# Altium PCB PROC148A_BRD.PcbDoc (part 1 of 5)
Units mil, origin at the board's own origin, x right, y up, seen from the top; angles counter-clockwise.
Board outline 7150 x 3764 mil, 4 copper layers (Top Layer, GND01, PWR/GND02, Bottom Layer), stack 60.96 mil thick; 312 components, 352 nets, 2206 pads, 423 vias.
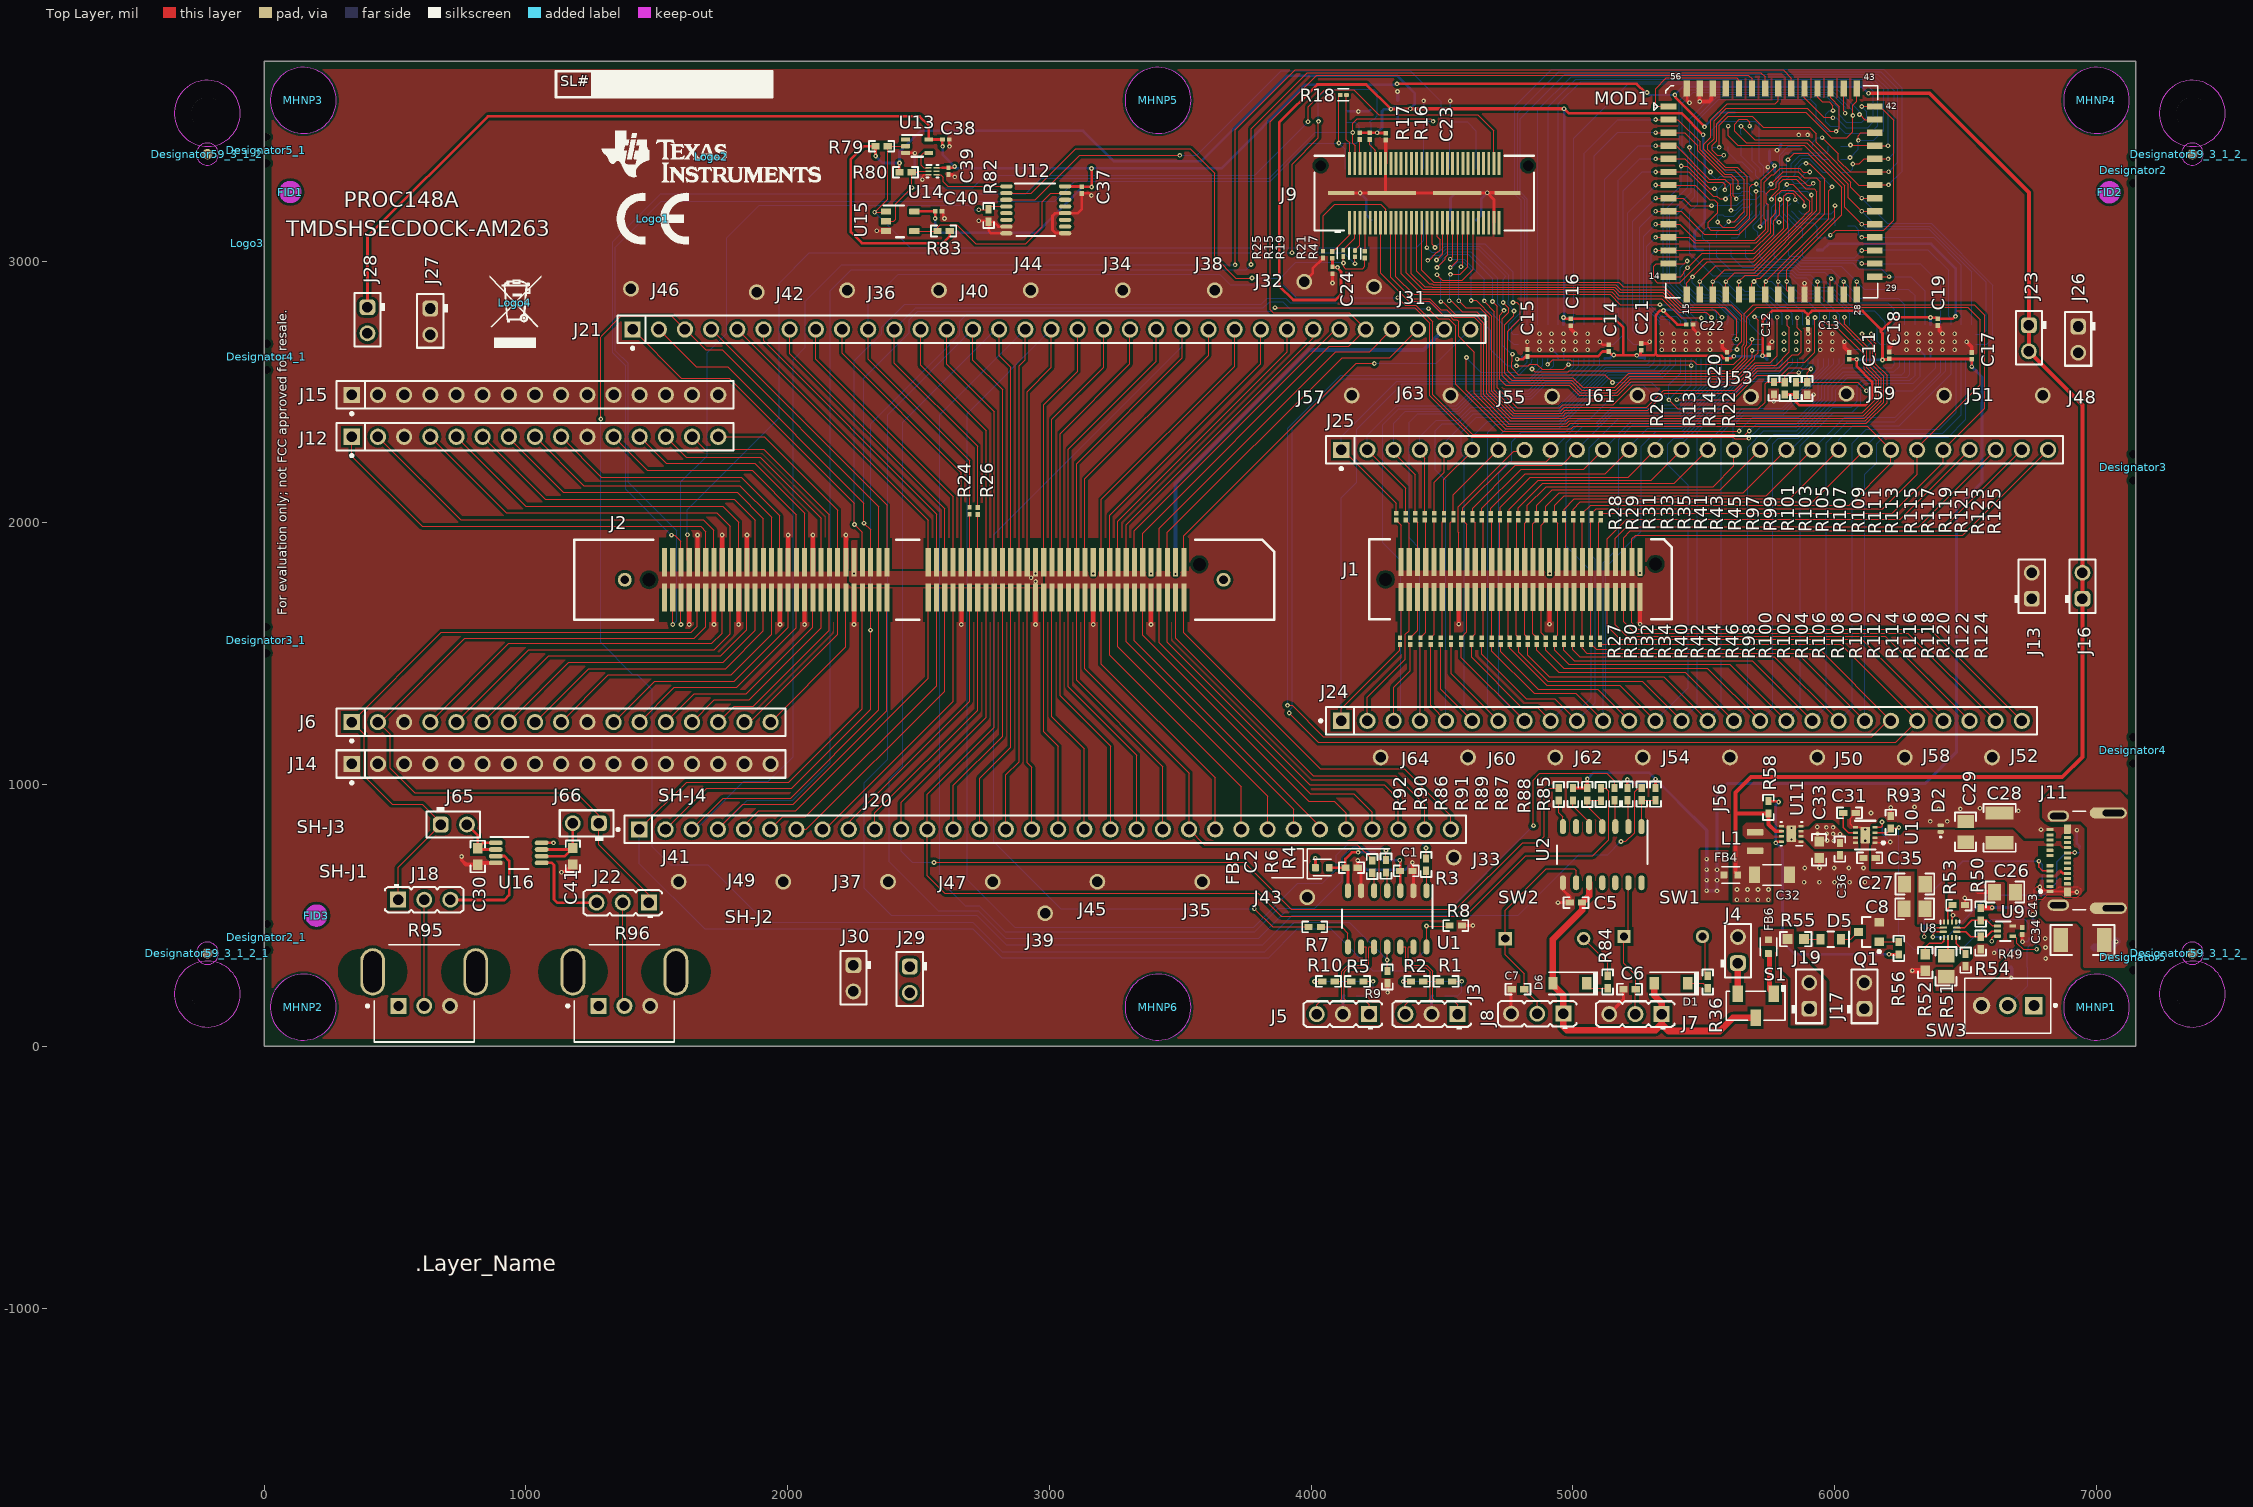
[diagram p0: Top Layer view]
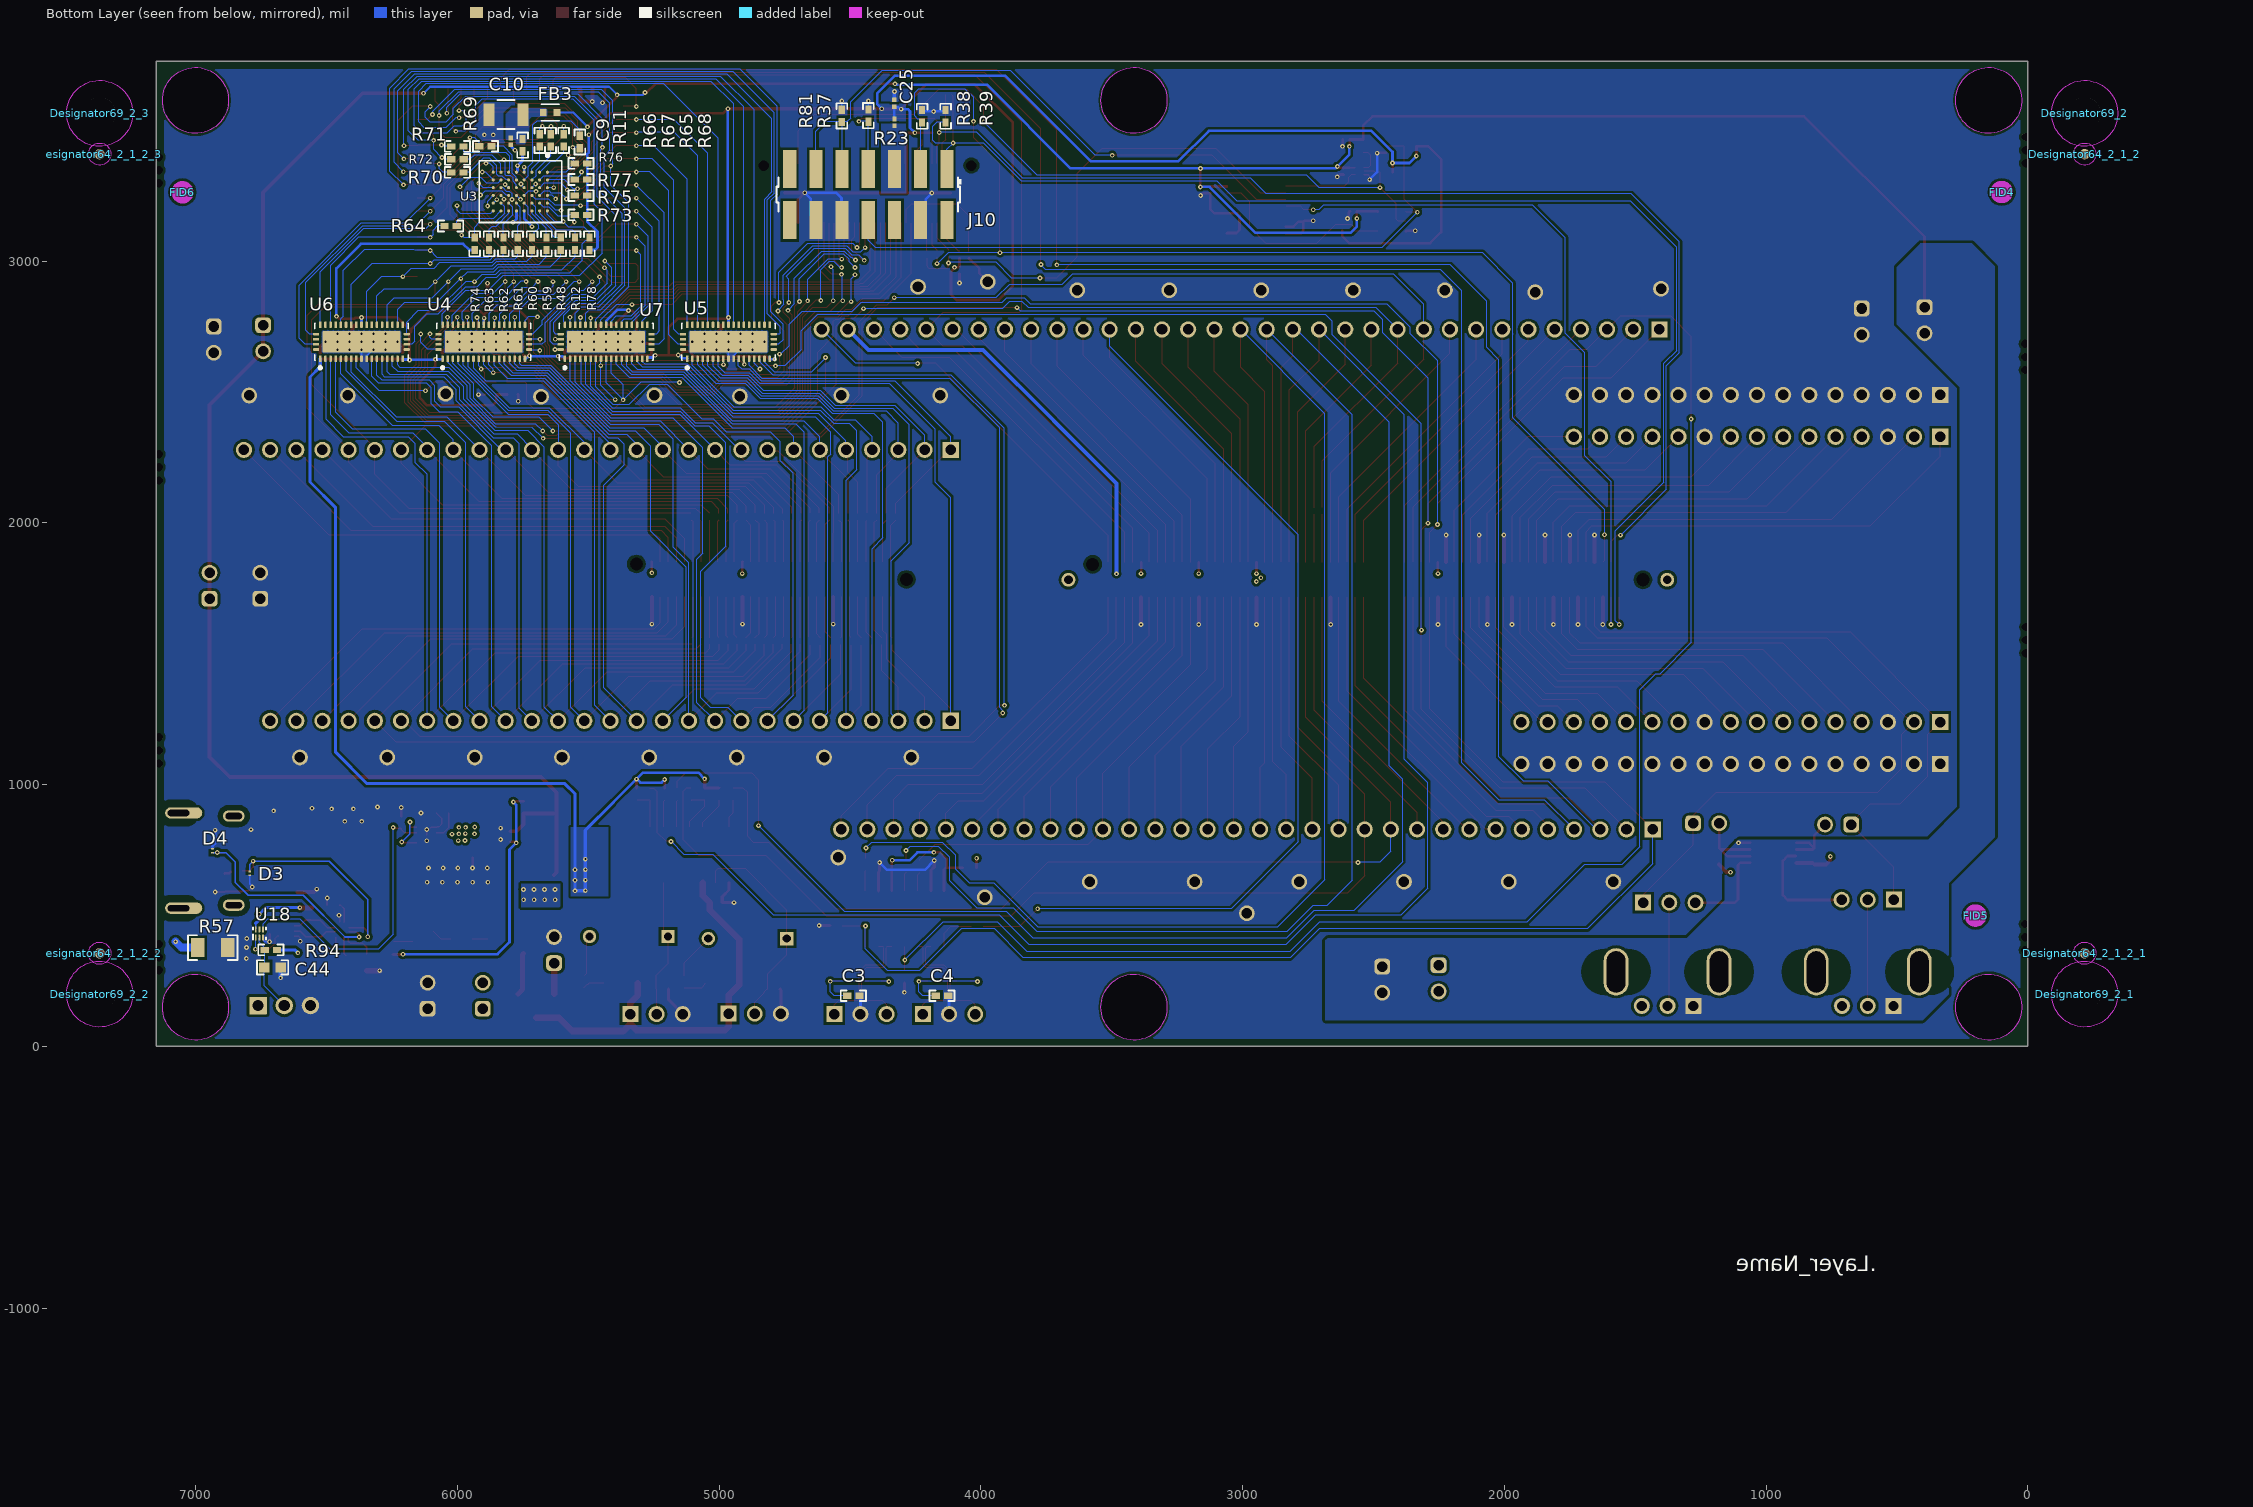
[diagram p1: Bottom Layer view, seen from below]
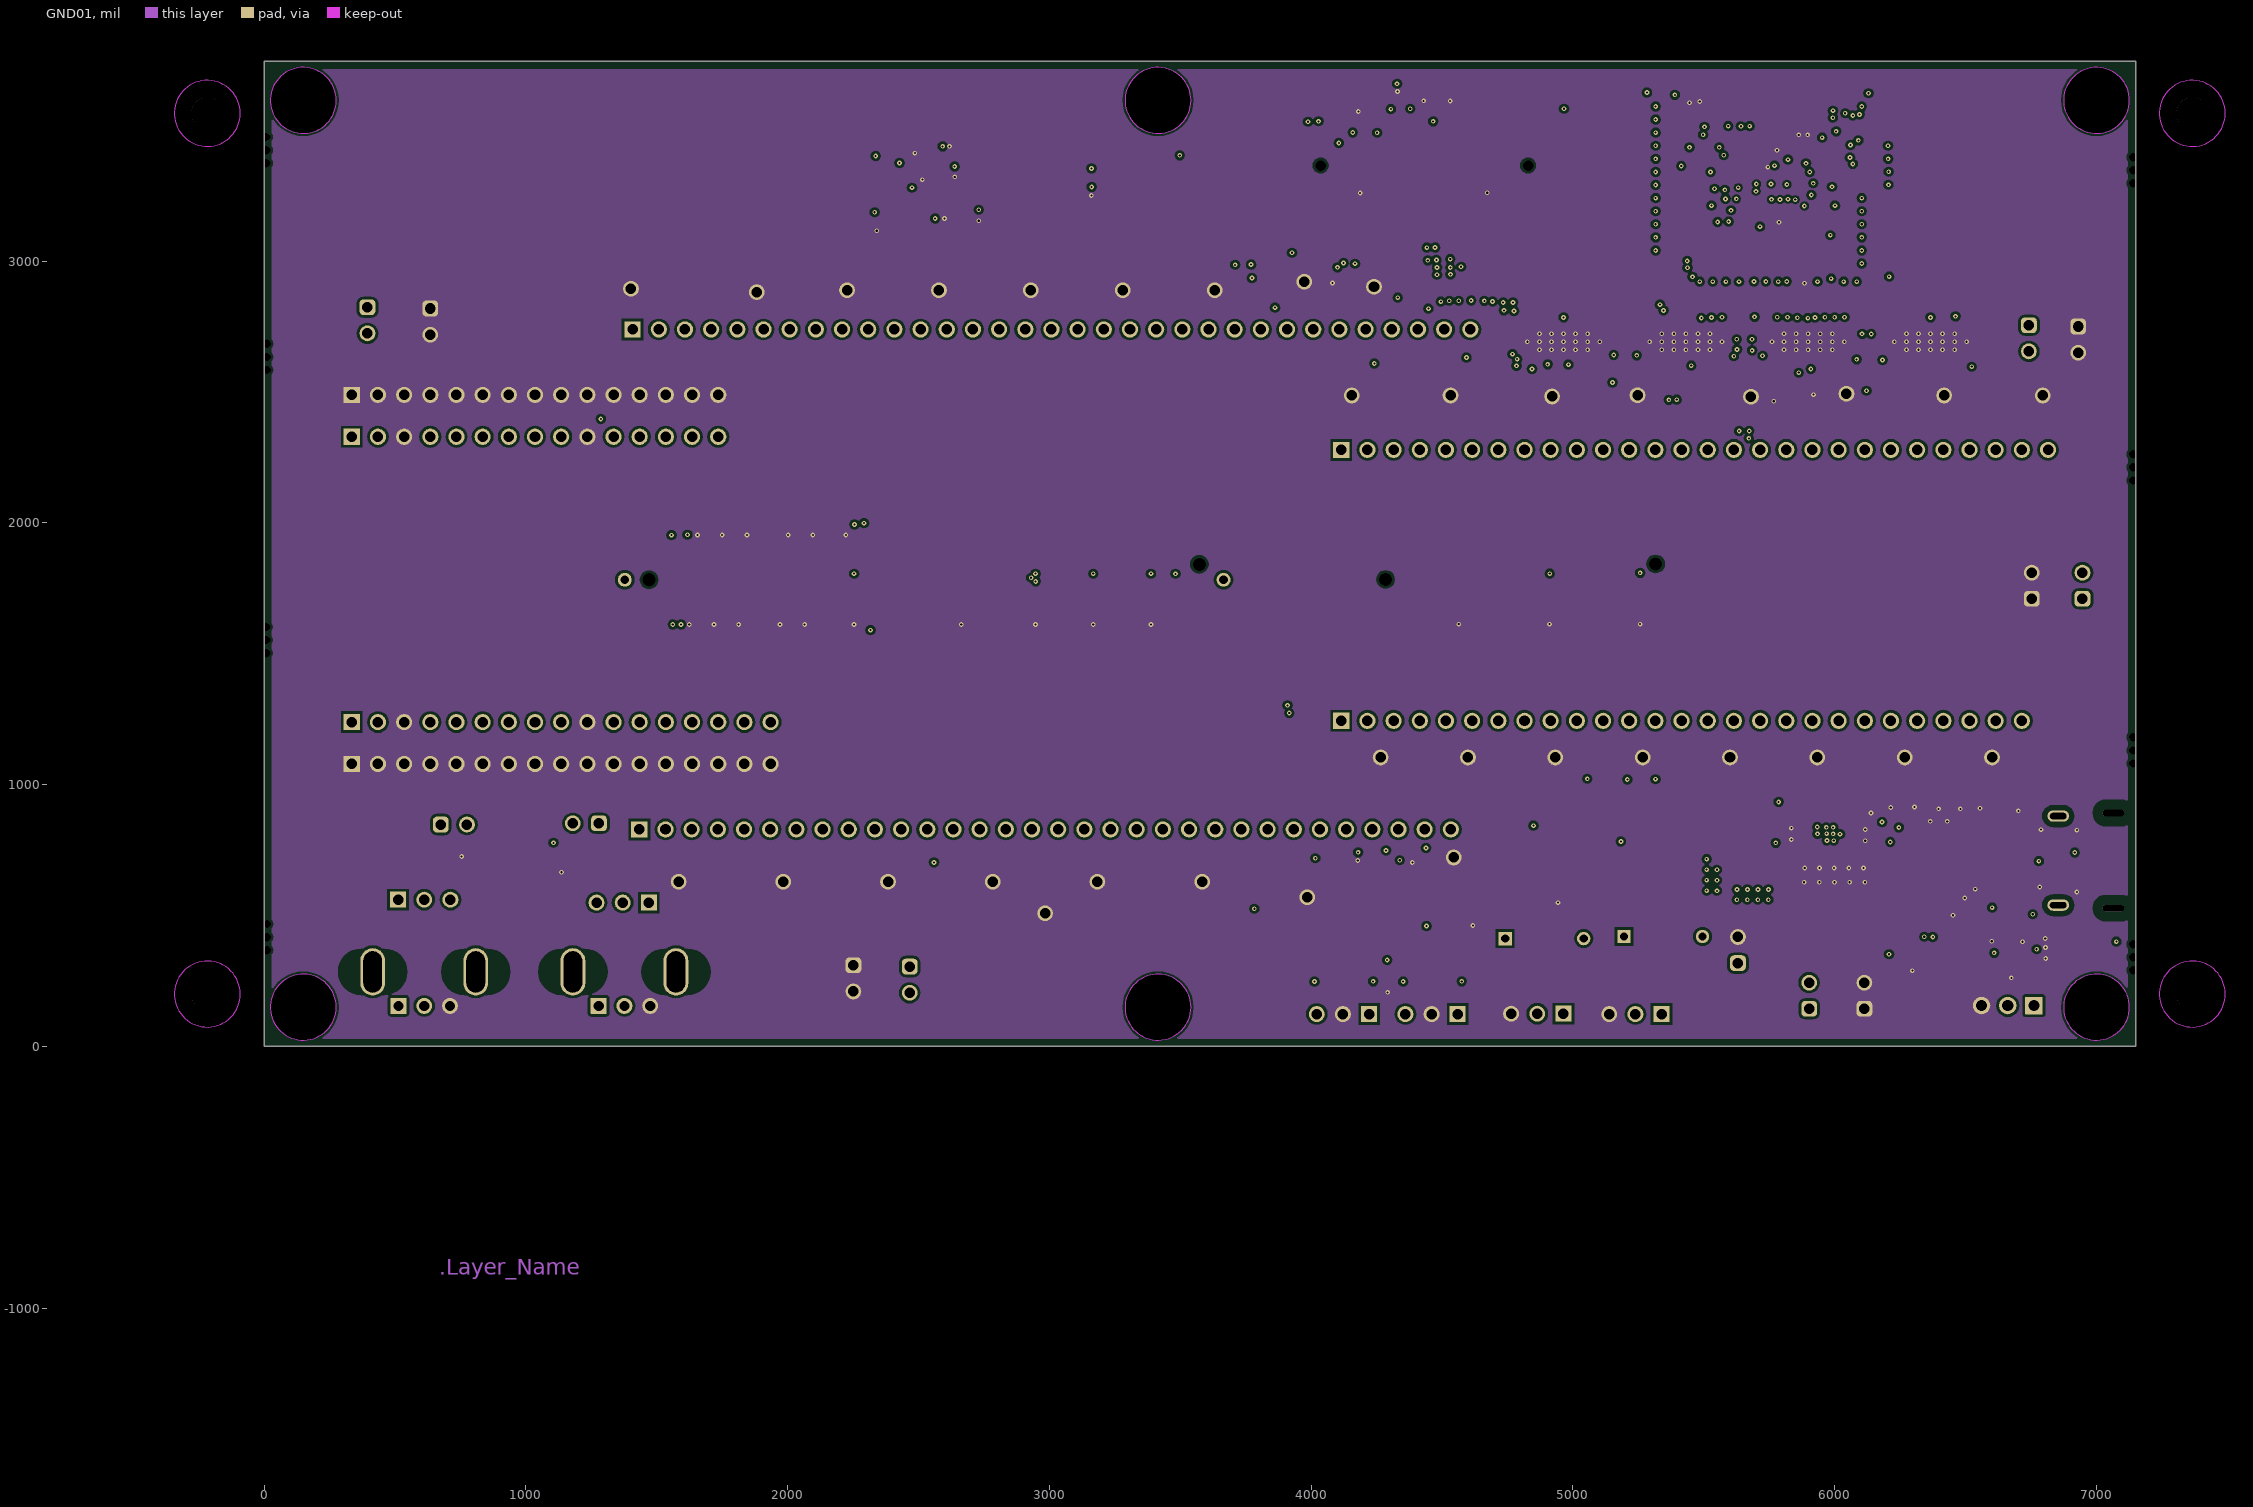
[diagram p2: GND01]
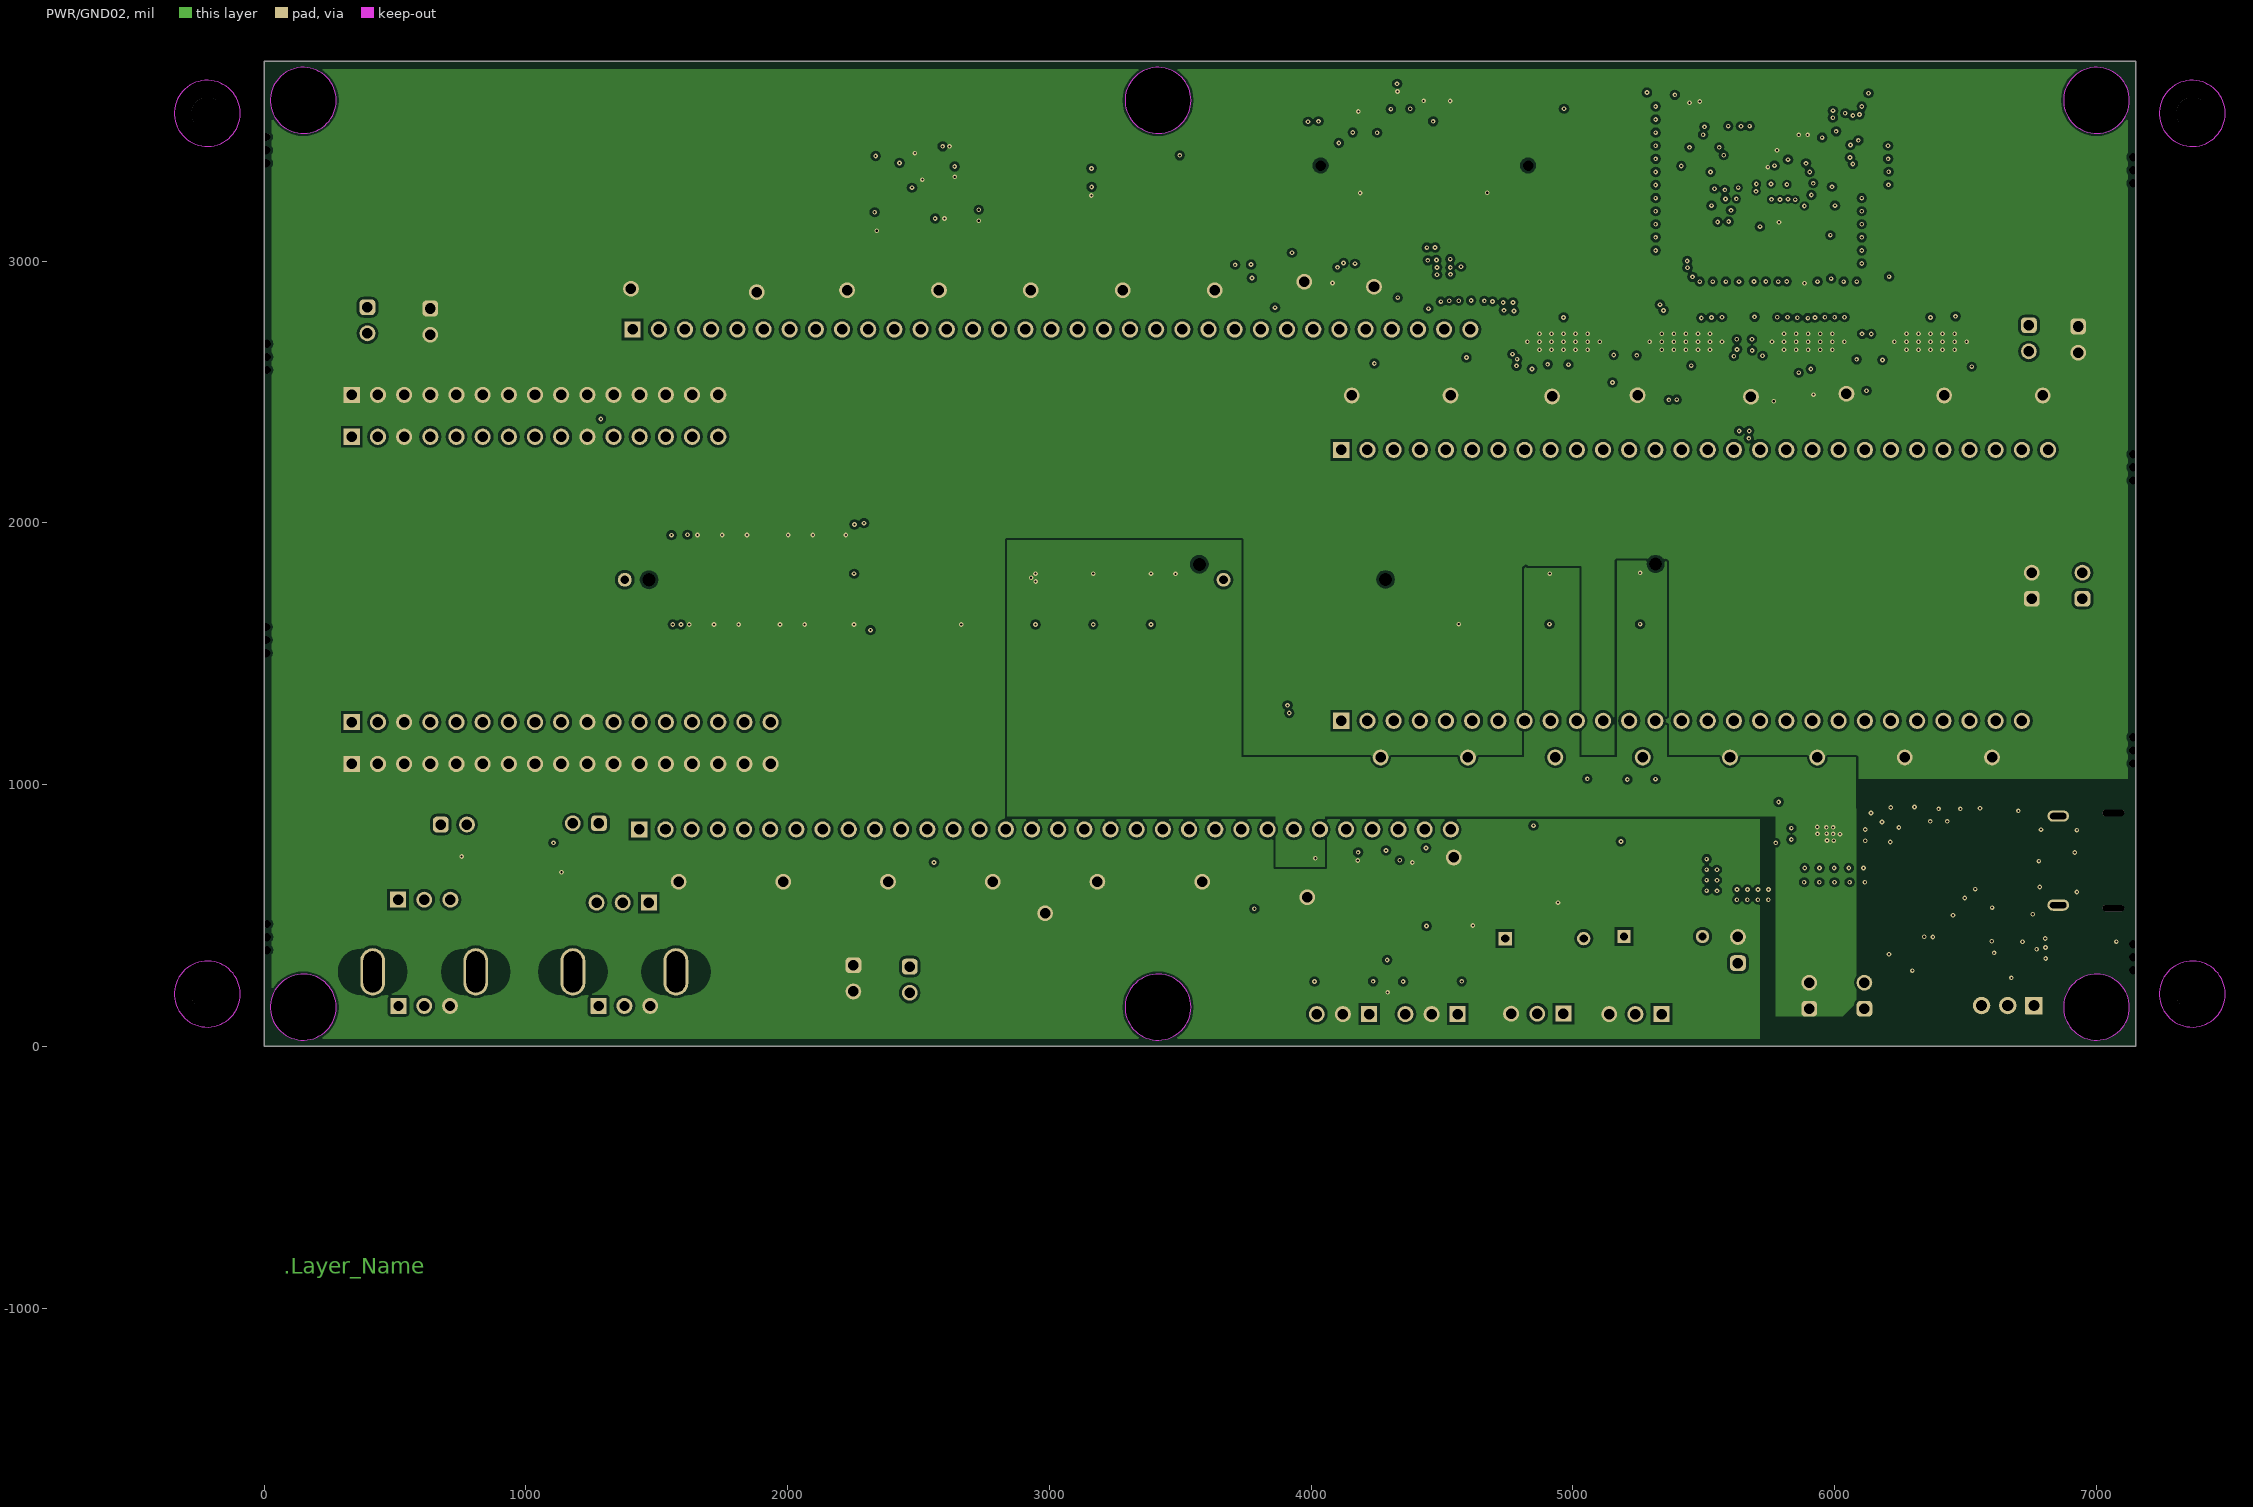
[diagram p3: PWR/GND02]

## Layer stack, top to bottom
Top Solder: solder mask 1, Solder Resist, Dk 3.5
Top Layer: signal copper 1.4
Dielectric 2: prepreg 3.7, FR-4, Dk 4.1
GND01: signal copper 1.38
Dielectric 1: dielectric 48, FR-4, Dk 4.8
PWR/GND02: signal copper 1.38
Dielectric 3: prepreg 3.7, FR-4, Dk 4.1
Bottom Layer: signal copper 1.4
Bottom Solder: solder mask 1, Solder Resist, Dk 3.5

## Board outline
-0.08,0 -0.08,3764 7149.92,3764 7149.92,0

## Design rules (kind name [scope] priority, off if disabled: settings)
AcuteAngle [All] p1: minimum=4.50000000000000E+0001 checktracksonly=FALSE
AssemblyTestPointUsage [All] p1: valid=2
BoardOutlineClearance BoardOutlineClearance_1 [All] p1: gap=30 ignorepadtopadclearanceinfootprint=FALSE
BoardOutlineClearance BoardOutlineClearance_MountingHoles [OnCopper and InComponentClass('Mounting Holes')] p2: gap=40 ignorepadtopadclearanceinfootprint=FALSE
BoardOutlineClearance BoardOutlineClearance_Poly [OnCopper and IsPoly] p3: gap=25 ignorepadtopadclearanceinfootprint=FALSE
BoardOutlineClearance [OnCopper and Not InComponentClass('Logo') and not InComponentClass('FiducialMark') and not InRegion(1000,500,4000,800) and not InPoly] p4: gap=40 ignorepadtopadclearanceinfootprint=FALSE
Clearance Clearance_room [WithinRoom('RoomDefinition')] p1: gap=7.87 ignorepadtopadclearanceinfootprint=TRUE except(4: Arc-Arc Arc-Track Track-Track Track-SMDPad Track-Via SMDPad-Via)
Clearance Clearance_Keepouts [((IsTrack Or IsArc) And Not InPoly) And IsFree and IsKeepOut vs ((IsTrack Or IsArc) And Not InPoly) And IsFree and IsKeepOut] p2: gap=0 ignorepadtopadclearanceinfootprint=FALSE
Clearance Clearance_Poly [InPolygon] p3: gap=10 ignorepadtopadclearanceinfootprint=TRUE
Clearance Clearance_FiducialMark [IsKeepOut and InComponentClass('FiducialMark') vs IsPad and InComponentClass('FiducialMark')] p4: gap=8 ignorepadtopadclearanceinfootprint=FALSE
Clearance [All] p5: gap=7.87 ignorepadtopadclearanceinfootprint=TRUE except(5: Arc-Arc Arc-Track Track-Track; 6: SMDPad-Via; 7: Arc-SMDPad Track-SMDPad)
ComponentClearance ComponentClearance_MountingHoles_FiducialMarks [InComponentClass('Mounting Holes') vs InComponentClass('FiducialMark')] p1: gap=50 collisioncheckmode=3 verticalgap=10 showdistances=FALSE
ComponentClearance ComponentClearance_Shunt [InComponentClass('Header') vs InComponentClass('Shunt')] p2: gap=0 collisioncheckmode=3 verticalgap=0 showdistances=FALSE
ComponentClearance ComponentClearance_Logo [InComponentClass('Logo')] p3: gap=30 collisioncheckmode=3 verticalgap=10 showdistances=FALSE
ComponentClearance ComponentClearance_ScrewToNut [(HasFootprint('NY PMS 440 0025 PH')) vs (HasFootprint('Keystone_1902C'))] p4: gap=5 collisioncheckmode=3 verticalgap=10 showdistances=FALSE
ComponentClearance ComponentClearance_MountingHoles [InComponentClass('Mounting Holes')] p5: gap=100 collisioncheckmode=3 verticalgap=100000 showdistances=FALSE
ComponentClearance ComponentClearance_SmallPassives [HasFootprint('0201*') or HasFootprint('0402*') or HasFootprint('0508') or HasFootprint('0603*') or HasFootprint('0612') or HasFootprint('0805*') or HasFootprint('0815*') or HasFootprint('0830*') or HasFootprint('1206*') or HasFootprint('1210*') or HasFootprint('1808*') or HasFootprint('1812*') or HasFootprint('1825*') or HasFootprint('2010*') or HasFootprint('2220*') or HasFootprint('2225*') or HasFootprint('2512*') or HasFootprint('2728*') or HasFootprint('3518*') vs HasFootprint('0201*') or HasFootprint('0402*') or HasFootprint('0508') or HasFootprint('0603*') or HasFootprint('0612') or HasFootprint('0805*') or HasFootprint('0815*') or HasFootprint('0830*') or HasFootprint('1206*') or HasFootprint('1210*') or HasFootprint('1808*') or HasFootprint('1812*') or HasFootprint('1825*') or HasFootprint('2010*') or HasFootprint('2220*') or HasFootprint('2225*') or HasFootprint('2512*') or HasFootprint('2728*') or HasFootprint('3518*')] p6: gap=14.96 collisioncheckmode=3 verticalgap=10 showdistances=FALSE
ComponentClearance ComponentClearance_THtoSMT [IsThruComponent vs IsSMTComponent] p7: gap=30 collisioncheckmode=3 verticalgap=30 showdistances=FALSE
ComponentClearance ComponentClearance_THtoTH [IsThruComponent vs IsThruComponent] p8: gap=20 collisioncheckmode=3 verticalgap=30 showdistances=FALSE
ComponentClearance [All] p9: gap=20 collisioncheckmode=3 verticalgap=10 showdistances=FALSE
DiffPairsRouting [All] p1: maxlimit=5 minlimit=5 mostfreqgap=5 toplayer_minwidth=4 toplayer_maxwidth=4 toplayer_prefwidth=4 midlayer1_minwidth=4 midlayer1_maxwidth=4 midlayer1_prefwidth=4 midlayer2_minwidth=4 midlayer2_maxwidth=4 midlayer2_prefwidth=4 bottomlayer_minwidth=4 bottomlayer_maxwidth=4 bottomlayer_prefwidth=4 maxuncoupledlength=1000
DiffPairsRouting DiffPairsRouting_1 [All] p2: maxlimit=10 minlimit=10 mostfreqgap=10 toplayer_minwidth=15 toplayer_maxwidth=15 toplayer_prefwidth=15 midlayer1_minwidth=15 midlayer1_maxwidth=15 midlayer1_prefwidth=15 midlayer2_minwidth=15 midlayer2_maxwidth=15 midlayer2_prefwidth=15 bottomlayer_minwidth=15 bottomlayer_maxwidth=15 bottomlayer_prefwidth=15 maxuncoupledlength=500
FabricationTestPointUsage TestPointUsage [All] p1: valid=2 allowmultiple=FALSE
FabricationTestpoint Testpoint [All] p1: side=3 testpointundercomponent=TRUE minsize=40 maxsize=100 preferedsize=60 minholesize=0 maxholesize=40 preferedholesize=32 testpointgrid=1 allowsidetop=TRUE allowsidebottom=TRUE usegrid=TRUE gridtolerance=0.01
FanoutControl Fanout_LCC [IsLCC] p1: bgadir=Out bgaviamode=Centered fanoutstyle=Auto fanoutdirection=Alternating viagrid=1 // Fanout_LCC (Default Rule)
FanoutControl Fanout_BGA [IsBGA] p2: bgadir=Out bgaviamode=Centered fanoutstyle=BGA fanoutdirection=Alternating viagrid=1 // Fanout_BGA (Default Rule)
FanoutControl Fanout_Default [All] p4: bgadir=Out bgaviamode=Centered fanoutstyle=Auto fanoutdirection=Alternating viagrid=1 // Fanout_Default (Default Rule)
FanoutControl Fanout_Small [(CompPinCount < 5)] p5: bgadir=Out bgaviamode=Centered fanoutstyle=Auto fanoutdirection=OutThenIn viagrid=1 // Fanout_Small (Default Rule)
HoleSize [All] p1: absolutevalues=TRUE maxlimit=251 minlimit=7.87 maxpercent=80.000 minpercent=20.000
MinimumAnnularRing MinimumAnnularRing_ThermalPadVias [IsVia and InAnyComponent] p1: minimumring=5.91
MinimumAnnularRing [All] p2: minimumring=7.87
MinimumSolderMaskSliver MinimumSolderMaskSliver_Logo [InComponentClass('Logo') vs InComponentClass('Logo')] p1: minsoldermaskwidth=0.7
MinimumSolderMaskSliver [All] p2: minsoldermaskwidth=3.94
PlaneConnect [All] p1: planeconnectstyle=Relief reliefexpansion=10 reliefentries=4 reliefconductorwidth=10 reliefairgap=10
PolygonConnect [All] p1: connectstyle=Direct reliefconductorwidth=10 reliefentries=4 polygonreliefangle="90 Angle" airgapwidth=10
RoomDefinition [All vs False] p1: confinementstyle=ConfineOut formatcopy=TRUE lockcomponents=FALSE outline 5885,3364.82 5885,3170 5620,3170 5620,3364.82
RoutingLayers [All] p1: top layer_v5=TRUE mid layer 1_v5=FALSE mid layer 2_v5=FALSE bottom layer_v5=TRUE
RoutingVias [All] p1: holewidth=8 width=18 viastyle="Through Hole" minholewidth=8 minwidth=18 maxholewidth=8 maxwidth=18
RoutingVias RoutingVias_1 [InNetClass('All Nets')] p2: holewidth=28 width=50 viastyle="Through Hole" minholewidth=28 minwidth=50 maxholewidth=28 maxwidth=50
RoutingVias ThermalPadVias [IsVia and InAnyComponent] p3: holewidth=7.87 width=19.68 viastyle="Through Hole" minholewidth=7.87 minwidth=19.68 maxholewidth=12.99 maxwidth=23.62
SilkToSilkClearance SilkToSilkClearance_Pb-FreeLogo [(HasFootprint('Pb-Free_Overlay_Medium') OR HasFootprint('Pb-Free_Overlay_Small')) vs (HasFootprint('Pb-Free_Overlay_Medium') OR HasFootprint('Pb-Free_Overlay_Small'))] p1: silktosilkclearance=0
SilkToSilkClearance [All] p2: silktosilkclearance=3.94
SilkToSolderMaskClearance SilkToComponentPadClearance [(IsPad or IsFill or IsRegion) and InAnycomponent] p1: minsilkscreentomaskgap=5 clearancetoexposedcopper=TRUE
SilkToSolderMaskClearance "Silk to Solder Mask Opening" [All] p2: minsilkscreentomaskgap=3.94 clearancetoexposedcopper=FALSE
SolderMaskExpansion [All] p1: expansion=1.97 istentingtop=FALSE
UnRoutedNet [All] p1: checkbadconnections=TRUE
Width [All] p1: maxlimit=100 minlimit=4 preferedwidth=10 minimp=50.000000 maximp=50.000000 favimp=50.000000 checkconnectedcopper=TRUE
Width Width_1_BGA [WithinRoom('RoomDefinition') and OnBottomLayer] p2: maxlimit=10 minlimit=4 preferedwidth=10 toplayer_prefwidth=6 bottomlayer_prefwidth=6 minimp=50.000000 maximp=50.000000 favimp=50.000000
Width Width_2 [All] p3: maxlimit=10 minlimit=4 preferedwidth=10 minimp=50.000000 maximp=50.000000 favimp=50.000000
14 further rules are at their usual default settings.

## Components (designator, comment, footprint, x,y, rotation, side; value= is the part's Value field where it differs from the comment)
C1 "GRM155R71H104ME14D" 0402 4363.3,670.72 r0 top value=0.1uF
C2 "GRM155R71H104ME14D" 0402 4154.41,682.92 r0 top value=0.1uF
C3 "GRM155R72A472KA01D" 0402 4486.92,193.67 r180 bottom value=4700pF
C4 "GRM155R72A472KA01D" 0402 4148.4,193.67 r180 bottom value=4700pF
C5 "GRM155R71H104ME14D" 0402 5011.47,549.3 r180 top value=0.1uF
C6 "CGA2B2X8R1H221K050BA" 0402 5216.38,218.72 r180 top value=220pF
C7 "CGA2B2X8R1H221K050BA" 0402 4790,218.72 r180 top value=220pF
C8 "C0805C104M5RACTU" 0805_HV 6305,525.7 r180 top value=0.1uF
C9 "GRM033R61C104KE84D" 0201_033 5795.28,3457.77 r270 bottom value=0.1uF
C10 "GRJ32ER71H106KE11L" 1210_280 5813.81,3559.69 r0 bottom value=10uF
C11 "GRM033R61C104KE84D" 0201_033 6056.15,2638.35 r90 top value=0.1uF
C12 "GRM033R61C104KE84D" 0201_033 5748.48,2654.85 r90 top value=0.1uF
C13 "GRM033R61C104KE84D" 0201_033 5897.7,2752.4 r270 top value=0.1uF
C14 "GRM033R61C104KE84D" 0201_033 5137.39,2667.55 r90 top value=0.1uF
C15 "GRM033R61C104KE84D" 0201_033 4826.2,2648.99 r90 top value=0.1uF
C16 "GRM033R61C104KE84D" 0201_033 4991.7,2766.4 r270 top value=0.1uF
C17 "GRM033R61C104KE84D" 0201_033 6523.45,2638.35 r90 top value=0.1uF
C18 "GRM033R61C104KE84D" 0201_033 6208.57,2639.88 r90 top value=0.1uF
C19 "GRM033R61C104KE84D" 0201_033 6393.6,2766.77 r270 top value=0.1uF
C20 "GRM033R61C104KE84D" 0201_033 5588.8,2638.4 r90 top value=0.1uF
C21 "GRM033R61C104KE84D" 0201_033 5261.18,2672.5 r90 top value=0.1uF
C22 "GRM033R61C104KE84D" 0201_033 5446.1,2757.6 r0 top value=0.1uF
C23 "GRM033R61C104KE84D" 0201_033 4284.88,3475.55 r270 top value=0.1uF
C24 "GRM033R61C104KE84D" 0201_033 4081.68,2965.16 r270 top value=0.1uF
C25 "GRM033R61C104KE84D" 0201_033 4330.71,3603.13 r90 bottom value=0.1uF
C26 "C0805C104M5RACTU" 0805_HV 6650,589.92 r180 top value=0.1uF
C27 "C0805C104M5RACTU" 0805_HV 6306,620 r180 top value=0.1uF
C28 "CL32B106KBJNNWE" 1210_270 6630,834.8 r90 top value=10uF
C29 "C0805C104M5RACTU" 0805_HV 6500,820 r90 top value=0.1uF
C30 "GRM1885C1H301JA01D" 0603 816.38,725.71 r270 top value=300pF
C31 "GRM1555C1H102JA01D" 0402 6056.38,891.89 r0 top value=1000pF
C32 "GRM31CR71A226KE15L" 1206_180 5760.43,655 r0 top value=22uF
C33 "GRT188R61E106ME13D" 0603 5940.74,751.5 r90 top value=10uF
C34 "GR442QR73D102KW01L" 1808 6946.55,406.81 r0 top value=1000pF
C35 "GRM155R61E105KA12D" 0402 6133.62,720 r180 top value=1uF
C36 "GRM155R61E105KA12D" 0402 6020,753.62 r270 top value=1uF
C37 "GRM033R61C104KE84D" 0201_033 3124.18,3271.58 r270 top value=0.1uF
C38 "GRM033R61C104KE84D" 0201_033 2604.29,3464.55 r0 top value=0.1uF
C39 "GRM033R61C104KE84D" 0201_033 2614.29,3344.12 r270 top value=0.1uF
C40 "GRM033R61C104KE84D" 0201_033 2576.96,3190.55 r0 top value=0.1uF
C41 "GRM1885C1H301JA01D" 0603 1179.55,726.69 r270 top value=300pF
C43 "GRM033R61C104KE84D" 0201_033 6716.04,441.02 r270 top value=0.1uF
C44 "GRM1885C1H103JA01D" 0603 6705.5,302 r180 bottom value=0.01uF
D1 "1N4148W-7-F" SOD-123 5374.47,240.72 r180 top value=100V
D2 "TPD1E05U06QDPYRQ1" DPY0002A 6404.97,832.15 r90 top
D3 "TPD1E01B04DPLR" DPL0002A 6792.77,661.37 r90 bottom
D4 "TPD1E01B04DPLR" DPL0002A 6935,747.42 r270 bottom
D5 "LP M67K-D2G1-25-Z" LP-M67K_Green 5985,410 r0 top value=Green
D6 "1N4148W-7-F" SOD-123 4988.22,240.72 r180 top value=100V
Designator2 "Comment" BRAKE_WAY_HOLES1X3 7189.29,3346.79 r90 top
Designator2_1 "Comment" BRAKE_WAY_HOLES1X3 -39.29,417.76 r270 top
Designator3 "Comment" BRAKE_WAY_HOLES1X3 7189.29,2212.03 r90 top
Designator3_1 "Comment" BRAKE_WAY_HOLES1X3 -41.15,1552.52 r270 top
Designator4 "Comment" BRAKE_WAY_HOLES1X3 7188.88,1130.65 r90 top
Designator4_1 "Comment" BRAKE_WAY_HOLES1X3 -38.88,2633.9 r270 top
Designator5 "Comment" BRAKE_WAY_HOLES1X3 7189.29,340.36 r90 top
Designator5_1 "Comment" BRAKE_WAY_HOLES1X3 -40.39,3424.19 r270 top
Designator59_3_1_2 "Comment" FID_40X80 -216.54,3408.55 r180 top
Designator59_3_1_2_1 "Comment" FID_40X80 -216.53,355.99 r0 top
Designator59_3_1_2_2 "Comment" FID_40X80 7366.38,355.99 r0 top
Designator59_3_1_2_3 "Comment" FID_40X80 7366.37,3408.55 r180 top
Designator64_2_1_2 "Comment" FID_40X80 -216.54,3408.55 r0 bottom
Designator64_2_1_2_1 "Comment" FID_40X80 -216.53,355.99 r180 bottom
Designator64_2_1_2_2 "Comment" FID_40X80 7366.38,355.99 r180 bottom
Designator64_2_1_2_3 "Comment" FID_40X80 7366.37,3408.55 r0 bottom
Designator69_2 "Comment" MHNP_M3_PANHEAD_PHILLIPS#1 -216.54,3564.55 r0 bottom
Designator69_2_1 "Comment" MHNP_M3_PANHEAD_PHILLIPS#1 -216.53,200 r180 bottom
Designator69_2_2 "Comment" MHNP_M3_PANHEAD_PHILLIPS#1 7366.38,200 r180 bottom
Designator69_2_3 "Comment" MHNP_M3_PANHEAD_PHILLIPS#1 7366.37,3564.55 r0 bottom
FB3 "BLM18EG121SN1D" FP-BLM18EG121SN1D_0603-MFG 5645.5,3567.82 r0 bottom
FB4 "BLM18EG121SN1D" FP-BLM18EG121SN1D_0603-MFG 5603.43,655 r180 top
FB5 "BLM18EG121SN1D" FP-BLM18EG121SN1D_0603-MFG 4043.03,682.92 r0 top
FB6 "BLM18EG121SN1D" FP-BLM18EG121SN1D_0603-MFG 5746.82,381.31 r270 top
FID1 "Fiducial" Fiducial10-20 100,3264 r0 top
FID2 "Fiducial" Fiducial10-20 7050,3263.02 r0 top
FID3 "Fiducial" Fiducial10-20 200,500 r0 top
FID4 "Fiducial" Fiducial10-20 100,3264 r180 bottom
FID5 "Fiducial" Fiducial10-20 200,500 r180 bottom
FID6 "Fiducial" Fiducial10-20 7050,3263.02 r180 bottom
J1 "HSEC8-130-01-L-DV-A" controlCARD-180HSEC-60pinAddon 4800,1784 r0 top locked
J2 "HSEC8-160-01-L-DV-A-BL" controlCARD-120HSEC 2449.17,1781.79 r0 top locked
J3 "22284033" Molex_0022284033 4459.94,123.67 r180 top
J4 "TSW-102-08-G-S" Samtec_TSW-102-08-x-S 5630.35,368.23 r90 top
J5 "22284033" Molex_0022284033 4121.41,123.67 r180 top
J6 "TSW-117-23-T-S" FP-TSW-117-23-T-S-MFG 1135,1239 r0 top
J7 "22284033" Molex_0022284033 5238.62,123.66 r180 top
J8 "22284033" Molex_0022284033 4863.69,125 r180 top
J9 "Receptacle_30x2_4MP_LeftRight" Samtec_QSH-030-01-X-D-A 4432.27,3260.09 r90 top
J10 "TSM-107-01-L-DV" Samtec_TSM-107-01-x-DV 4430,3254.2 r270 bottom
J11 "2012670005" FP-2012670005_CONN_USB_9MM39_8MM21-MFG 6980,710 r90 top
J12 "TSW-115-23-T-S" FP-TSW-115-23-T-S-MFG 1035,2329 r0 top
J13 "TSW-102-08-G-S" Samtec_TSW-102-08-x-S 6752.87,1759.98 r90 top
J14 "TSW-117-23-T-S" FP-TSW-117-23-T-S-MFG 1135,1079 r0 top
J15 "TSW-115-23-T-S" FP-TSW-115-23-T-S-MFG 1035,2489 r0 top
J16 "TSW-102-08-G-S" Samtec_TSW-102-08-x-S 6946.42,1759.98 r90 top
J17 "TSW-102-08-G-S" Samtec_TSW-102-08-x-S 6113.46,193.66 r90 top
J18 "22284033" Molex_0022284033 611.85,560.53 r0 top
J19 "TSW-102-08-G-S" Samtec_TSW-102-08-x-S 5902.46,193.66 r90 top
J20 "TSW-132-23-T-S" FP-TSW-132-23-T-S-MFG 2983.54,829 r0 top locked
J21 "TSW-133-23-T-S" FP-TSW-133-23-T-S-MFG 3007.95,2739 r0 top
J22 "22284033" Molex_0022284033 1370,549.3 r180 top
J23 "TSW-102-08-G-S" Samtec_TSW-102-08-x-S 6741.81,2705.22 r270 top
J24 "TSW-127-23-T-S" FP-TSW-127-23-T-S-MFG 5415,1244 r0 top
J25 "TSW-128-23-T-S" FP-TSW-128-23-T-S-0 5465,2279 r0 top
J26 "TSW-102-08-G-S" Samtec_TSW-102-08-x-S 6930,2700.22 r270 top
J27 "TSW-102-08-G-S" Samtec_TSW-102-08-x-S 635,2769 r270 top
J28 "TSW-102-08-G-S" Samtec_TSW-102-08-x-S 395,2774 r270 top
J29 "TSW-102-08-G-S" Samtec_TSW-102-08-x-S 2466.37,254.94 r270 top
J30 "TSW-102-08-G-S" Samtec_TSW-102-08-x-S 2251.37,259.94 r270 top
J31 "TSW-101-08-G-S" Samtec_TSW-101-08-x-S 4240.07,2901.87 r0 top
J32 "TSW-101-08-G-S" Samtec_TSW-101-08-x-S 3974.04,2921.24 r0 top
J33 "TSW-101-08-G-S" Samtec_TSW-101-08-x-S 4544.29,721.89 r0 top
J34 "TSW-101-08-G-S" Samtec_TSW-101-08-x-S 3280.29,2889 r0 top
J35 "TSW-101-08-G-S" Samtec_TSW-101-08-x-S 3583.54,629 r0 top
J36 "TSW-101-08-G-S" Samtec_TSW-101-08-x-S 2227.12,2889 r0 top
J37 "TSW-101-08-G-S" Samtec_TSW-101-08-x-S 2383.54,629 r0 top
J38 "TSW-101-08-G-S" Samtec_TSW-101-08-x-S 3631.35,2889 r0 top
J39 "TSW-101-08-G-S" Samtec_TSW-101-08-x-S 2983.54,508.47 r0 top
J40 "TSW-101-08-G-S" Samtec_TSW-101-08-x-S 2578.17,2889 r0 top
J41 "TSW-101-08-G-S" Samtec_TSW-101-08-x-S 1583.54,629 r0 top
J42 "TSW-101-08-G-S" Samtec_TSW-101-08-x-S 1882.4,2881.6 r0 top
J43 "TSW-101-08-G-S" Samtec_TSW-101-08-x-S 3985,570 r0 top
J44 "TSW-101-08-G-S" Samtec_TSW-101-08-x-S 2929.23,2889 r0 top
J45 "TSW-101-08-G-S" Samtec_TSW-101-08-x-S 3183.54,629 r0 top
J46 "TSW-101-08-G-S" Samtec_TSW-101-08-x-S 1401.7,2894.3 r0 top
J47 "TSW-101-08-G-S" Samtec_TSW-101-08-x-S 2783.54,629 r0 top
J48 "TSW-101-08-G-S" Samtec_TSW-101-08-x-S 6795,2486.7 r0 top
J49 "TSW-101-08-G-S" Samtec_TSW-101-08-x-S 1983.54,629 r0 top
J50 "TSW-101-08-G-S" Samtec_TSW-101-08-x-S 5933.69,1104 r0 top
J51 "TSW-101-08-G-S" Samtec_TSW-101-08-x-S 6417.9,2486.7 r0 top
J52 "TSW-101-08-G-S" Samtec_TSW-101-08-x-S 6601.04,1104 r0 top
J53 "TSW-101-08-G-S" Samtec_TSW-101-08-x-S 5680.2,2482.22 r0 top
J54 "TSW-101-08-G-S" Samtec_TSW-101-08-x-S 5266.33,1104 r0 top
J55 "TSW-101-08-G-S" Samtec_TSW-101-08-x-S 4920.31,2482.99 r0 top
J56 "TSW-101-08-G-S" Samtec_TSW-101-08-x-S 5600.01,1104 r0 top
J57 "TSW-101-08-G-S" Samtec_TSW-101-08-x-S 4155.27,2486.7 r0 top
J58 "TSW-101-08-G-S" Samtec_TSW-101-08-x-S 6267.37,1104 r0 top
J59 "TSW-101-08-G-S" Samtec_TSW-101-08-x-S 6044.93,2493.36 r0 top
J60 "TSW-101-08-G-S" Samtec_TSW-101-08-x-S 4598.98,1104 r0 top
J61 "TSW-101-08-G-S" Samtec_TSW-101-08-x-S 5246.86,2487.85 r0 top
J62 "TSW-101-08-G-S" Samtec_TSW-101-08-x-S 4932.66,1104 r0 top
J63 "TSW-101-08-G-S" Samtec_TSW-101-08-x-S 4532.38,2486.7 r0 top
J64 "TSW-101-08-G-S" Samtec_TSW-101-08-x-S 4265.3,1104 r0 top
J65 "TSW-102-08-G-S" Samtec_TSW-102-08-x-S 725.16,847.74 r0 top
J66 "TSW-102-08-G-S" Samtec_TSW-102-08-x-S 1229.46,852.31 r180 top
L1 "TFM201610ALMA2R2MTAA" TFM201610ALMA 5696.11,782.9 r270 top value=2.2uH
Logo1 "CE Mark" CE_Mark_5mm 1485,3162 r0 top
Logo2 "Texas Instruments" TI_Stacked_Overlay_Small 1709,3399 r0 top
Logo3 "FCC disclaimer" FCC_disclaimer -65.04,3068.5 r90 top
Logo4 "WEEE logo" WEEE_Minimum 958.54,2840.61 r0 top
MHNP1 "Comment" MHNP_M3_PANHEAD_PHILLIPS#2 7000,150 r180 top
MHNP2 "Comment" MHNP_M3_PANHEAD_PHILLIPS#2 150,150 r90 top
MHNP3 "Comment" MHNP_M3_PANHEAD_PHILLIPS#2 150,3614 r0 top
MHNP4 "Comment" MHNP_M3_PANHEAD_PHILLIPS#2 7000,3614 r270 top
MHNP5 "Comment" MHNP_M3_PANHEAD_PHILLIPS#2 3415,3614 r0 top
MHNP6 "Comment" MHNP_M3_PANHEAD_PHILLIPS#2 3415,150 r0 top
MOD1 "MSPL_GPMC_MOD" MSPL_GPMC_MOD 5759.29,3265.66 r0 top locked
Q1 "BSS138LT1G" ONSC-SOT-23-3-318-08_V 6130.63,437.4 r180 top
R1 "CRCW040259R0FKED" 0402 4514.9,248.46 r180 top value=59.0
R2 "CRCW040259R0FKED" 0402 4404.9,248.46 r180 top value=59.0
R3 "CRCW04020000Z0ED" 0402 4438.92,694.73 r270 top value=0
R4 "CRCW040233R0JNED" 0402 4285.8,688.47 r270 top value=33
R5 "CRCW040259R0FKED" 0402 4176.38,248.46 r180 top value=59.0
R6 "CRCW04020000Z0ED" 0402 4233.03,687.09 r270 top value=0
R7 "CRCW040233R0JNED" 0402 4013.71,456.6 r0 top value=33
R8 "ERJ-2GEJ103X" 0402 4552.4,461.6 r180 top value=10k
R9 "ERJ-2GEJ103X" 0402 4291.3,265 r90 top value=10k
R10 "CRCW040259R0FKED" 0402 4066.38,248.46 r180 top value=59.0
R11 "CRCW0402110RJNED" 0402 5750.74,3443.08 r90 bottom value=110
R12 "CRCW040222R0JNED" 0402 5550.01,3066.28 r270 bottom value=22
R13 "CRCW040210K0JNED" 0402 5809.01,2514 r270 top value=10k
R14 "CRCW040210K0JNED" 0402 5851.61,2513.36 r270 top value=10k
R15 "CRCW0201100RFKED" 0201 4081.19,3024.19 r270 top value=100
R16 "CRCW0201100RFKED" 0201 4223.99,3477.51 r90 top value=100
R17 "CRCW02014K70FKED" 0201_033 4186.1,3477.51 r90 top value=4.70k
R18 "ERJ-1GNF33R2C" FP-ERJ-1GNF33R2C_0201-IPC_B 4122.92,3634.74 r0 top value=33.2
R19 "ERJ-1GNF33R2C" FP-ERJ-1GNF33R2C_0201-IPC_B 4122.5,3029.51 r270 top value=33.2
R20 "CRCW040210K0JNED" 0402 5767.99,2514.34 r90 top value=10k
R21 "ERJ-1GNF33R2C" FP-ERJ-1GNF33R2C_0201-IPC_B 4167.39,3028.53 r270 top value=33.2
R22 "CRCW040210K0JNED" 0402 5895.27,2513.57 r90 top value=10k
R23 "CRCW0201100RFKED" 0201 4329.6,3529.99 r90 bottom value=100
R24 "RC0201FR-0710RL" 0201 2694.96,2046.49 r90 top value=10.0
R25 "CRCW02010000Z0ED" 0201 4045.41,3024.65 r90 top value=0
R26 "RC0201FR-0710RL" 0201 2726.45,2045.49 r90 top value=10.0
R27 "RC0201FR-0710RL" 0201 4339.35,1547.99 r90 top value=10.0
R28 "RC0201FR-0710RL" 0201 4325,2024 r90 top value=10.0
R29 "RC0201FR-0710RL" 0201 4361.43,2024 r90 top value=10.0
R30 "RC0201FR-0710RL" 0201 4378.37,1547.99 r90 top value=10.0
R31 "RC0201FR-0710RL" 0201 4397.86,2024 r90 top value=10.0
R32 "RC0201FR-0710RL" 0201 4417.4,1547.99 r90 top value=10.0
R33 "RC0201FR-0710RL" 0201 4434.29,2024 r90 top value=10.0
R34 "RC0201FR-0710RL" 0201 4456.43,1547.99 r90 top value=10.0
R35 "RC0201FR-0710RL" 0201 4470.71,2024 r90 top value=10.0
R36 "CRCW04021K00FKED" 0402 5515,246.22 r270 top value=1.00k
R37 "CRCW040210K0JNED" 0402 4429.6,3555.62 r270 bottom value=10k
R38 "CRCW040210K0JNED" 0402 4224.6,3553.38 r270 bottom value=10k
R39 "CRCW040210K0JNED" 0402 4134.6,3553.38 r270 bottom value=10k
R40 "RC0201FR-0710RL" 0201 4495.46,1547.99 r90 top value=10.0
R41 "RC0201FR-0710RL" 0201 4507.14,2024 r90 top value=10.0
R42 "RC0201FR-0710RL" 0201 4534.48,1547.99 r90 top value=10.0
R43 "RC0201FR-0710RL" 0201 4543.57,2024 r90 top value=10.0
R44 "RC0201FR-0710RL" 0201 4573.51,1547.99 r90 top value=10.0
R45 "RC0201FR-0710RL" 0201 4580,2024 r90 top value=10.0
R46 "RC0201FR-0710RL" 0201 4612.54,1547.99 r90 top value=10.0
R47 "ERJ-1GNJ220C" 0201 4204.97,3025.08 r90 top value=22
R48 "CRCW040222R0JNED" 0402 5604.8,3066.28 r270 bottom value=22
R49 "ERJ-2RKF4701X" 0402 6557.59,395.31 r90 top value=4.70k
R50 "ERJ-2RKF4701X" 0402 6557.59,505.2 r270 top value=4.70k
R51 "ERJ-6ENF9093V" 0805_HV 6425.4,306.34 r90 top value=909k
R52 "CRCW06034K70JNEA" 0603 6346,320.2 r270 top value=4.7k
R53 "CRCW04020000Z0ED" 0402 6474.01,540.03 r180 top value=0
R54 "ERJ-2RKF2003X" 0402 6500,329.69 r90 top value=200k
R55 "CRCW0603220RJNEA" 0603 5851.5,410.07 r180 top value=220
R56 "CRCW04020000Z0ED" 0402 6245,375 r270 top value=0
R57 "CRCW12061M00FKEA" 1206 6934.71,377.36 r180 bottom value=1.00Meg
R58 "CRCW0402100KFKED" 0402 5746.82,913.57 r90 top value=100k
R59 "CRCW040222R0JNED" 0402 5659.59,3066.28 r270 bottom value=22
R60 "CRCW040222R0JNED" 0402 5714.38,3066.28 r270 bottom value=22
R61 "CRCW040222R0JNED" 0402 5769.17,3066.28 r270 bottom value=22
R62 "CRCW040222R0JNED" 0402 5823.95,3066.28 r270 bottom value=22
R63 "CRCW040222R0JNED" 0402 5878.74,3066.28 r270 bottom value=22
R64 "CRCW040222R0JNED" 0402 6025.28,3134.19 r0 bottom value=22
R65 "CRCW040222R0JNED" 0402 5593.58,3461.25 r90 bottom value=22
R66 "CRCW040222R0JNED" 0402 5685.09,3461.37 r90 bottom value=22
R67 "CRCW040222R0JNED" 0402 5643.28,3461.25 r90 bottom value=22
R68 "CRCW040222R0JNED" 0402 5531.88,3454.83 r270 bottom value=22
R69 "CRCW040222R0JNED" 0402 5892.49,3438.83 r0 bottom value=22
R70 "CRCW040222R0JNED" 0402 5999.82,3339.05 r0 bottom value=22
R71 "CRCW040222R0JNED" 0402 5999.84,3438.29 r0 bottom value=22
R72 "CRCW040222R0JNED" 0402 5999.26,3388.88 r0 bottom value=22
R73 "CRCW040210K0JNED" 0402 5527.52,3176.5 r180 bottom value=10k
R74 "CRCW040210K0JNED" 0402 5933.53,3066.28 r270 bottom value=10k
R75 "CRCW040210K0JNED" 0402 5527.62,3250.4 r180 bottom value=10k
R76 "CRCW040210K0JNED" 0402 5527.62,3373.4 r180 bottom value=10k
R77 "CRCW040210K0JNED" 0402 5527.62,3311.9 r180 bottom value=10k
R78 "CRCW040210K0JNED" 0402 5495.22,3066.28 r270 bottom value=10k
R79 "CRCW040210K0JNED" 0402 2359.29,3438.96 r180 top value=10k
R80 "CRCW040210K0JNED" 0402 2450.67,3339.55 r180 top value=10k
R81 "CRCW040210K0JNED" 0402 4531,3555.08 r270 bottom value=10k
R82 "CRCW040210K0JNED" 0402 2767.9,3174.3 r90 top value=10k
R83 "CRCW040210K0JNED" 0402 2596.02,3115.05 r0 top value=10k
R84 "CRCW04021K00FKED" 0402 5132.72,246.22 r270 top value=1.00k
R85 "CRCW040210K0JNED" 0402 5315.34,963.62 r90 top value=10k
R86 "CRCW040210K0JNED" 0402 5054.88,963.16 r90 top value=10k
R87 "CRCW040210K0JNED" 0402 5207.87,963.62 r270 top value=10k
R88 "CRCW040233R0JNED" 0402 5262.77,963.62 r270 top value=33
R89 "CRCW04020000Z0ED" 0402 5159.37,963.62 r270 top value=0
R90 "CRCW040210K0JNED" 0402 4999.88,963.16 r270 top value=10k
R91 "CRCW040233R0JNED" 0402 5106.88,962.24 r270 top value=33
R92 "CRCW04020000Z0ED" 0402 4945.86,963.16 r270 top value=0
R93 "CRCW040210K0JNED" 0402 6214.01,856.46 r270 top value=10k
R94 "CRCW0402100KFKED" 0402 6712.29,369 r0 bottom value=100k
R95 "PTV09A-8025U-B103" FP-PTV09A-8025U-B103_PTH_POT_27MM4_9MM7-MFG 611.85,-160.17 r0 top value=10kO
R96 "PTV09A-8025U-B103" FP-PTV09A-8025U-B103_PTH_POT_27MM4_9MM7-MFG 1376.57,-160.17 r0 top value=10kO
R97 "RC0201FR-0710RL" 0201 4616.63,2022.99 r90 top value=10.0
R98 "RC0201FR-0710RL" 0201 4651.56,1547.99 r90 top value=10.0
R99 "RC0201FR-0710RL" 0201 4651.56,2022.99 r90 top value=10.0
R100 "RC0201FR-0710RL" 0201 4689.76,1548.5 r90 top value=10.0
R101 "RC0201FR-0710RL" 0201 4686.5,2022.99 r90 top value=10.0
R102 "RC0201FR-0710RL" 0201 4724.26,1548.5 r90 top value=10.0
R103 "RC0201FR-0710RL" 0201 4721.43,2022.99 r90 top value=10.0
R104 "RC0201FR-0710RL" 0201 4758.75,1548.5 r90 top value=10.0
R105 "RC0201FR-0710RL" 0201 4756.36,2022.99 r90 top value=10.0
R106 "RC0201FR-0710RL" 0201 4793.25,1548.5 r90 top value=10.0
R107 "RC0201FR-0710RL" 0201 4791.3,2022.99 r90 top value=10.0
R108 "RC0201FR-0710RL" 0201 4827.74,1548.5 r90 top value=10.0
R109 "RC0201FR-0710RL" 0201 4826.23,2022.99 r90 top value=10.0
R110 "RC0201FR-0710RL" 0201 4862.23,1548.5 r90 top value=10.0
R111 "RC0201FR-0710RL" 0201 4861.16,2022.99 r90 top value=10.0
R112 "RC0201FR-0710RL" 0201 4896.73,1548.5 r90 top value=10.0
R113 "RC0201FR-0710RL" 0201 4896.1,2022.99 r90 top value=10.0
R114 "RC0201FR-0710RL" 0201 4931.22,1548.5 r90 top value=10.0
R115 "RC0201FR-0710RL" 0201 4931.03,2022.99 r90 top value=10.0
R116 "RC0201FR-0710RL" 0201 4965.72,1548.5 r90 top value=10.0
R117 "RC0201FR-0710RL" 0201 4965.97,2022.99 r90 top value=10.0
R118 "RC0201FR-0710RL" 0201 5000.21,1548.5 r90 top value=10.0
R119 "RC0201FR-0710RL" 0201 5000.9,2022.99 r90 top value=10.0
R120 "RC0201FR-0710RL" 0201 5034.71,1548.5 r90 top value=10.0
R121 "RC0201FR-0710RL" 0201 5035.83,2022.99 r90 top value=10.0
R122 "RC0201FR-0710RL" 0201 5069.2,1548.5 r90 top value=10.0
R123 "RC0201FR-0710RL" 0201 5070.77,2022.99 r90 top value=10.0
R124 "RC0201FR-0710RL" 0201 5103.69,1548.5 r90 top value=10.0
R125 "RC0201FR-0710RL" 0201 5105.7,2022.99 r90 top value=10.0
S1 "CAS-120TA" SW_CAS-120TA 5698.22,155.28 r270 top
SH-J1 "60900213421" Wurth_60900213421 334.92,560.53 r180 top
SH-J2 "60900213421" Wurth_60900213421 1629.92,494.18 r180 top
SH-J3 "60900213421" Wurth_60900213421 491.8,841.83 r180 top
SH-J4 "60900213421" Wurth_60900213421 1361.32,957.95 r180 top
SW1 "A6TN-1104" FP-A6TN-1104_PTH_SW_7MM50_4MM48-MFG 5345,420 r270 top
SW2 "A6TN-1104" FP-A6TN-1104_PTH_SW_7MM50_4MM48-MFG 4891.02,412.09 r270 top
SW3 "200AWMSP1T1A1M2QE" FP-200AWMSP1T1A1M2QE_PTH_SW_8MM13_5MM08-MFG 6661,156 r180 top
U1 "TCAN1046DRQ1" D0014A_N 4290.64,487.26 r270 top
U2 "TLIN2022DRQ1" D0014A_N 5111.97,732.45 r270 top
U3 "IS67WVE4M16EBLL-70BLA1" FP-IS67WVE4M16EBLL-70BLA1_TFBGA48-IPC_C 5759.29,3265.71 r270 bottom
U4 "TS3DDR3812RUAR" RUA0042A-MFG 5898.72,2691.88 r90 bottom
U5 "TS3DDR3812RUAR" RUA0042A-MFG 4964.12,2691.88 r90 bottom
U6 "TS3DDR3812RUAR" RUA0042A-MFG 6366.02,2691.88 r90 bottom
U7 "TS3DDR3812RUAR" RUA0042A-MFG 5431.42,2691.88 r90 bottom
U8 "TUSB320IRWBR" RWB0012A 6440.59,445.94 r0 top
U9 "SN74AHC1G02DRLR" DRL0005A 6651.13,440.68 r0 top
U10 "TPS22965DSGT" FP-DSG0008A-MFG 6116.82,807.24 r180 top
U11 "TPS62172DSGT" DSG0008A 5834.41,812.07 r180 top
U12 "SN74CB3Q3257PWR" PW0016A_L 2947.91,3195.93 r0 top
U13 "SN74LVC1G04DCKR" DCK0005A_N 2495,3438.96 r0 top
U14 "SN74LVC1G08DSF2" DSF0006A 2553.54,3343.33 r0 top
U15 "SN74AHC1G02DBVT" DBV0005A_N 2430.16,3152.15 r0 top
U16 "OPA2837DGK" DGK0008A_N 972.76,739.51 r0 top
U18 "SN74LVC1G08DSF2" DSF0006A 6755.96,431.4 r90 bottom
ZZ1 "This Assembly Note is for PCB labels only" AssemblyNoteLabel 4385,4356 r0 top
ZZ2 "These assemblies are ESD sensitive, ESD precautions shall be observed." AssemblyNote 4385,4269.33 r0 top
ZZ3 "These assemblies must be clean and free from flux and all contaminants. Use of no clean flux is not acceptable." AssemblyNote 4385,4182.67 r0 top
ZZ4 "These assemblies must comply with workmanship standards IPC-A-610 Class 2, unless otherwise specified." AssemblyNote 4385,4096 r0 top

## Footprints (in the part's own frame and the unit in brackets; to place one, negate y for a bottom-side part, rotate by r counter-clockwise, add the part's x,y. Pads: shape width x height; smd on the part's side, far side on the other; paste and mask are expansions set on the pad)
0201 [mm] "Data from Kemet datasheet CC101_COM dated 7/28/11"
  rect 0.46x0.42 smd mask+0.048: 1(-0.33,0) 2(0.33,0)
  body extent -0.31,-0.16 0.31,0.16, height 0.26
0201_033 [mm] "SMD, 2-Leads, Height 0.33mm"
  rect 0.46x0.42 smd mask+0.048: 1(-0.33,0) 2(0.33,0)
  body extent -0.31,-0.16 0.31,0.16, height 0.33
0402 [mm] "0402 from SM-752 data"
  rect 0.8x0.6 smd: 1(-0.6,0) 2(0.6,0)
  silkscreen extent -1.22,-0.52 1.22,0.52, body extent -0.55,-0.3 0.55,0.3, height 0.6
0603 [mm] "0603 from SM-752 data"
  rect 1x0.95 smd: 1(-0.8,0) 2(0.8,0)
  silkscreen extent -1.52,-0.69 1.52,0.69, body extent -0.87,-0.47 0.87,0.47, height 1
0805_HV [mil] "0805 with 30mil clearance between pads"
  rect 50x63 smd: 1(-40,0) 2(40,0)
  silkscreen extent -74,-40 74,40, body extent -43,-29 43,29, height 57
1206 [mm] "1206 from SM-752 data"
  rect 1.3x1.85 smd: 1(-1.45,0) 2(1.45,0)
  silkscreen extent -2.4,-1.21 2.4,1.21, body extent -1.7,-0.9 1.7,0.9, height 1.35
1206_180 [mm] "1206_180"
  rect 1.1x1.6 smd: 1(-1.7,0) 2(1.7,0)
  silkscreen extent -0.9,-1 0.9,1, body extent -1.75,-0.95 1.75,0.95, height 1.8
1210_270 [mm] "1210"
  rect 1.3x2.7 smd: 1(-1.45,0) 2(1.45,0)
  silkscreen extent -2.32,-1.57 2.32,1.57, body extent -1.7,-1.35 1.7,1.35, height 2.7
1210_280 [mm] "SMD, 2-Leads, Body 3.6x2.8mm, Height 2.8mm"
  rect 1.1x2.2 smd: 1(-1.65,0) 2(1.65,0)
  silkscreen extent -0.84,-1.4 0.84,1.4, body extent -1.8,-1.4 1.8,1.4, height 2.8
1808 [mm] "Chip Capacitor, Body 4.6x2.0mm, IPC Medium Density"
  rect 1.4x2.3 smd: 1(-2.1,0) 2(2.1,0)
  silkscreen extent -3.1,-1.45 3.1,1.45, body extent -2.47,-1.2 2.47,1.2, height 2.03
AssemblyNote [mil] "Assembly Note"
AssemblyNoteLabel [mil] "Assembly Note for PCB Labels"
BRAKE_WAY_HOLES1X3 [mil]
  round 27 hole 32 unplated mask+5.5: ""(-50,49.37) ""(0,49.37) ""(50,49.37)
CE_Mark_5mm [mil] "Minimum text height for CE Mark"
  silkscreen extent -138,-98 138,98
controlCARD-120HSEC [mm] "Pads are not numbered according to Samtec datasheet."
  rect 0.5x2.724 smd: 1(-23.357,-1.678) 2(-23.357,1.722) 3(-22.557,-1.678) 4(-22.557,1.722) 5(-21.757,-1.678) 6(-21.757,1.722) 7(-20.957,-1.678) 8(-20.957,1.722) 9(-20.157,-1.678) 10(-20.157,1.722) 11(-19.357,-1.678) 12(-19.357,1.722) 13(-18.557,-1.678) 14(-18.557,1.722) 15(-17.757,-1.678) 16(-17.757,1.722) 17(-16.957,-1.678) 18(-16.957,1.722) 19(-16.157,-1.678) 20(-16.157,1.722) 21(-15.357,-1.678) 22(-15.357,1.722) 23(-14.557,-1.678) 24(-14.557,1.722) 25(-13.757,-1.678) 26(-13.757,1.722) 27(-12.957,-1.678) 28(-12.957,1.722) 29(-12.157,-1.678) 30(-12.157,1.722) 31(-11.357,-1.678) 32(-11.357,1.722) 33(-10.557,-1.678) 34(-10.557,1.722) 35(-9.757,-1.678) 36(-9.757,1.722) 37(-8.957,-1.678) 38(-8.957,1.722) 39(-8.157,-1.678) 40(-8.157,1.722) 41(-7.357,-1.678) 42(-7.357,1.722) 43(-6.557,-1.678) 44(-6.557,1.722) 45(-5.757,-1.678) 46(-5.757,1.722) 47(-4.957,-1.678) 48(-4.957,1.722) 49(-4.157,-1.678) 50(-4.157,1.722) 51(-3.357,-1.678) 52(-3.357,1.722) 53(-2.557,-1.678) 54(-2.557,1.722) 55(-1.757,-1.678) 56(-1.757,1.722) 57(2.243,-1.678) 58(2.243,1.722) 59(3.043,-1.678) 60(3.043,1.722) 61(3.843,-1.678) 62(3.843,1.722) 63(4.643,-1.678) 64(4.643,1.722) 65(5.443,-1.678) 66(5.443,1.722) 67(6.243,-1.678) 68(6.243,1.722) 69(7.043,-1.678) 70(7.043,1.722) 71(7.843,-1.678) 72(7.843,1.722) 73(8.643,-1.678) 74(8.643,1.722) 75(9.443,-1.678) 76(9.443,1.722) 77(10.243,-1.678) 78(10.243,1.722) 79(11.043,-1.678) 80(11.043,1.722) 81(11.843,-1.678) 82(11.843,1.722) 83(12.643,-1.678) 84(12.643,1.722) 85(13.443,-1.678) 86(13.443,1.722) 87(14.243,-1.678) 88(14.243,1.722) 89(15.043,-1.678) 90(15.043,1.722) 91(15.843,-1.678) 92(15.843,1.722) 93(16.643,-1.678) 94(16.643,1.722) 95(17.443,-1.678) 96(17.443,1.722) 97(18.243,-1.678) 98(18.243,1.722) 99(19.043,-1.678) 100(19.043,1.722) 101(19.843,-1.678) 102(19.843,1.722) 103(20.643,-1.678) 104(20.643,1.722) 105(21.443,-1.678) 106(21.443,1.722) 107(22.243,-1.678) 108(22.243,1.722) 109(23.043,-1.678) 110(23.043,1.722) 111(23.843,-1.678) 112(23.843,1.722) 113(24.643,-1.678) 114(24.643,1.722) 115(25.443,-1.678) 116(25.443,1.722) 117(26.243,-1.678) 118(26.243,1.722) 119(27.043,-1.678) 120(27.043,1.722)
  round 0.025 hole 1.27 unplated mask+0.876: 181(-24.857,0.022) 182(28.543,1.522)
  round 1.348 hole 0.84: 185(-27.207,0.022) 186(30.893,0.022)
  silkscreen extent -32.11,-3.86 35.8,3.9, body extent -31.75,-3.48 35.3,3.52, height 12.35
controlCARD-180HSEC-60pinAddon [mm] "Pads are not numbered according to datasheet."
  round 0.025 hole 1.27 unplated mask+0.876: 61(-13.1,0) 62(13.1,1.5)
  rect 0.5x2.724 smd: 121(-11.6,-1.7) 122(-11.6,1.7) 123(-10.8,-1.7) 124(-10.8,1.7) 125(-10,-1.7) 126(-10,1.7) 127(-9.2,-1.7) 128(-9.2,1.7) 129(-8.4,-1.7) 130(-8.4,1.7) 131(-7.6,-1.7) 132(-7.6,1.7) 133(-6.8,-1.7) 134(-6.8,1.7) 135(-6,-1.7) 136(-6,1.7) 137(-5.2,-1.7) 138(-5.2,1.7) 139(-4.4,-1.7) 140(-4.4,1.7) 141(-3.6,-1.7) 142(-3.6,1.7) 143(-2.8,-1.7) 144(-2.8,1.7) 145(-2,-1.7) 146(-2,1.7) 147(-1.2,-1.7) 148(-1.2,1.7) 149(-0.4,-1.7) 150(-0.4,1.7) 151(0.4,-1.7) 152(0.4,1.7) 153(1.2,-1.7) 154(1.2,1.7) 155(2,-1.7) 156(2,1.7) 157(2.8,-1.7) 158(2.8,1.7) 159(3.6,-1.7) 160(3.6,1.7) 161(4.4,-1.7) 162(4.4,1.7) 163(5.2,-1.7) 164(5.2,1.7) 165(6,-1.7) 166(6,1.7) 167(6.8,-1.7) 168(6.8,1.7) 169(7.6,-1.7) 170(7.6,1.7) 171(8.4,-1.7) 172(8.4,1.7) 173(9.2,-1.7) 174(9.2,1.7) 175(10,-1.7) 176(10,1.7) 177(10.8,-1.7) 178(10.8,1.7) 179(11.6,-1.7) 180(11.6,1.7)
  silkscreen extent -14.68,-3.88 14.68,3.88, body extent -14.3,-3.5 14.3,3.5, height 7.95
D0014A_N [mm] "SOIC, 14-Leads, Body 8.7x3.9mm, Pitch 1.27mm, IPC Medium Density"
  oval 1.45x0.6 smd: 1(-2.725,3.81) 2(-2.725,2.54) 3(-2.725,1.27) 4(-2.725,0) 5(-2.725,-1.27) 6(-2.725,-2.54) 7(-2.725,-3.81) 8(2.725,-3.81) 9(2.725,-2.54) 10(2.725,-1.27) 11(2.725,0) 12(2.725,1.27) 13(2.725,2.54) 14(2.725,3.81)
  silkscreen extent -3.3,-4.4 0.9,4.4, body extent -3.02,-4.32 3.02,4.32, height 1.6
DBV0005A_N [mm] "SOT23, 5-Leads, Body 2.9x1.6mm, Pitch 0.95mm, Lead Span 2.8mm, IPC Medium Density"
  rrect17% 1x0.6 smd: 1(-1.375,0.95) 2(-1.375,0) 3(-1.375,-0.95) 4(1.375,-0.95) 5(1.375,0.95)
  silkscreen extent -1.63,-1.55 0.38,1.55, body extent -1.42,-1.46 1.42,1.46, height 1.09
DCK0005A_N [mm] "SOT353, 5-Leads, Body 2x1.3mm, Pitch 0.65mm, Lead Span 2.1mm, IPC Medium Density"
  rrect25% 0.85x0.4 smd: 1(-1.125,0.65) 2(-1.125,0) 3(-1.125,-0.65) 4(1.125,-0.65) 5(1.125,0.65)
  silkscreen extent -1.48,-1.02 0.55,1.1, body extent -1.14,-1 1.14,1, height 0.95
DGK0008A_N [mm] "TSOP, 8-Leads, Body 3x3mm, Pitch 0.65mm, IPC Medium Density"
  oval 1.35x0.45 smd: 1(-2.225,0.975) 2(-2.225,0.325) 3(-2.225,-0.325) 4(-2.225,-0.975) 5(2.225,-0.975) 6(2.225,-0.325) 7(2.225,0.325) 8(2.225,0.975)
  silkscreen extent -2.75,-1.55 0.95,1.55, body extent -2.45,-1.5 2.45,1.5, height 0.96
DPL0002A [mm] "R-PX2SON-N2"
  rect 0.18x0.25 smd: 1(-0.193,0)
  rect 0.19x0.25 smd: 2(0.192,0)
  body extent -0.32,-0.17 0.32,0.17, height 0.32
DPY0002A [mm] "X1SON-2"
  rrect57% 0.35x0.6 smd paste-0.5 mask-0.05: 1(-0.325,0) 2(0.325,0)
  rrect33% 0.3x0.5 on Top Paste: 1S(-0.35,0) 2S(0.35,0)
  silkscreen extent -0.85,-0.03 -0.8,0.02, body extent -0.5,-0.3 0.5,0.3, height 0.45
DRL0005A [mm] "SOTFL, 5-Flat Leads, Body 1.2x1.6x0.6mm, Pitch 0.5mm, TI recommended"
  rrect33% 0.67x0.3 smd: 1(-0.74,0.5) 2(-0.74,0) 3(-0.74,-0.5) 4(0.74,-0.5) 5(0.74,0.5)
  silkscreen extent -0.9,-0.95 0.5,0.95, body extent -0.85,-0.85 0.85,0.85, height 0.62
DSF0006A [mm] "TI recommended land pattern"
  rrect59% 0.6x0.17 smd mask+0.045: 1(-0.4,0.35) 2(-0.4,0) 3(-0.4,-0.35) 4(0.4,-0.35) 5(0.4,0) 6(0.4,0.35)
  silkscreen extent -0.6,-0.63 0.6,0.63, body extent -0.5,-0.5 0.5,0.5, height 0.48
DSG0008A [mm] "SON, 8-Leads, Body 2x2mm, Pitch 0.5mm, Thermal Pad 1.6x0.9mm, TI Recommended"
  rrect40% 0.5x0.25 smd: 1(-0.95,0.75) 2(-0.95,0.25) 3(-0.95,-0.25) 4(-0.95,-0.75) 5(0.95,-0.75) 6(0.95,-0.25) 7(0.95,0.25) 8(0.95,0.75)
  rrect14% 0.9x0.7 on Top Paste: 9(0,0.45) 9(0,-0.45)
  rrect11% 0.9x1.6 smd paste-0.45: 9(0,0)
  silkscreen extent -1.07,-1.15 1.07,1.15, body extent -1,-1 1,1, height 0.77
FCC_disclaimer [mil]
FID_40X80 [mil]
  round 40 smd paste-20 mask+20: ""(0,0)
  Top Layer keep-out circle w1: c0,0 r42.5
Fiducial10-20 [mm]
  round 1 smd mask+0.5: 1(0,0)
  Top Layer keep-out circle w1.178: c0,0 r0.5
FP-200AWMSP1T1A1M2QE_PTH_SW_8MM13_5MM08-MFG [mm]
  rrect6% 1.69x1.69 hole 1.09 paste-1000 mask+0: 1(-2.54,0)
  round 1.69 hole 1.09 paste-1000 mask+0: 2(0,0) 3(2.54,0)
  silkscreen extent -4.75,-2.67 4.19,2.67, body extent -4.29,-2.77 4.29,2.77, height 0.25
FP-2012670005_CONN_USB_9MM39_8MM21-MFG [mm]
  rrect100% 1.1x2.1 hole 1.6 slot 0.6 at 0 deg paste-1000 mask+0: 1(-4.32,3.205) 2(4.32,3.205)
  rrect100% 0.6x2.1 hole 2.1 slot 0.6 at 0 deg paste-1000 mask+0: 3(-4.62,-2.155) 4(4.62,-2.155)
  rrect100% 1.1x3.6 smd paste-1000 mask+0: 3(-4.62,-1.655) 4(4.62,-1.655)
  rrect100% 1.1x3.6 smd far side paste-1000 mask+0: 3(-4.62,-1.655) 4(4.62,-1.655)
  rrect33% 0.3x0.7 smd paste+0 mask+0: A1(-3,4.015) A2(-2.5,4.015) A3(-2,4.015) A4(-1.5,4.015) A5(-1,4.015) A6(-0.5,4.015) A7(0.5,4.015) A8(1,4.015) A9(1.5,4.015) A10(2,4.015) A11(2.5,4.015) A12(3,4.015) B2(2.25,2.315) B3(1.75,2.315) B4(1.25,2.315) B5(0.75,2.315) B6(0.25,2.315) B7(-0.25,2.315) B8(-0.75,2.315) B9(-1.25,2.315) B10(-1.75,2.315) B11(-2.25,2.315)
  rrect14% 0.9x0.7 smd paste+0 mask+0: B1(3.05,2.315) B12(-3.05,2.315)
  silkscreen extent -4.77,0.52 4.77,5.03, body extent -5.27,-4.33 5.27,4.46, height 0.25
FP-A6TN-1104_PTH_SW_7MM50_4MM48-MFG [mm]
  rect 1.3x1.3 hole 0.8 paste-1000 mask+0: 1(0,-3.81)
  round 1.3 hole 0.8 paste-1000 mask+0: 2(0,3.81)
  body extent -2.59,-4.56 2.59,4.56, height 0.25
FP-BLM18EG121SN1D_0603-MFG [mm]
  rrect15% 0.65x0.7 smd paste+0 mask+0: 1(-0.675,0) 2(0.675,0)
  silkscreen extent -0.87,-0.8 0.87,0.8, body extent -0.8,-0.4 0.8,0.4, height 0.95
FP-DSG0008A-MFG [mm]
  rrect40% 0.5x0.25 smd paste+0 mask+0: 1(-0.95,0.75) 2(-0.95,0.25) 3(-0.95,-0.25) 4(-0.95,-0.75) 5(0.95,-0.75) 6(0.95,-0.25) 7(0.95,0.25) 8(0.95,0.75)
  rrect11% 0.9x1.6 smd paste-1000 mask+0: 9(0,0)
  silkscreen extent -1.88,-1.39 1,1.4, body extent -1.3,-1.15 1.3,1.15, height 0.25
FP-ERJ-1GNF33R2C_0201-IPC_B [mil]
  rrect28% 17.88x14.28 smd paste+0 mask+0: 1(-11.98,0) 2(11.98,0)
  silkscreen extent -21,-23 21,23, body extent -27,-13 27,13, height 10
FP-IS67WVE4M16EBLL-70BLA1_TFBGA48-IPC_C [mm]
  round 0.298 smd paste+0 mask+0: A1(-1.875,2.625) A2(-1.125,2.625) A3(-0.375,2.625) A4(0.375,2.625) A5(1.125,2.625) A6(1.875,2.625) B1(-1.875,1.875) B2(-1.125,1.875) B3(-0.375,1.875) B4(0.375,1.875) B5(1.125,1.875) B6(1.875,1.875) C1(-1.875,1.125) C2(-1.125,1.125) C3(-0.375,1.125) C4(0.375,1.125) C5(1.125,1.125) C6(1.875,1.125) D1(-1.875,0.375) D2(-1.125,0.375) D3(-0.375,0.375) D4(0.375,0.375) D5(1.125,0.375) D6(1.875,0.375) E1(-1.875,-0.375) E2(-1.125,-0.375) E3(-0.375,-0.375) E4(0.375,-0.375) E5(1.125,-0.375) E6(1.875,-0.375) F1(-1.875,-1.125) F2(-1.125,-1.125) F3(-0.375,-1.125) F4(0.375,-1.125) F5(1.125,-1.125) F6(1.875,-1.125) G1(-1.875,-1.875) G2(-1.125,-1.875) G3(-0.375,-1.875) G4(0.375,-1.875) G5(1.125,-1.875) G6(1.875,-1.875) H1(-1.875,-2.625) H2(-1.125,-2.625) H3(-0.375,-2.625) H4(0.375,-2.625) H5(1.125,-2.625) H6(1.875,-2.625)
  silkscreen extent -3.62,-4 3,4, body extent -3,-4 3,4, height 1.2
FP-PTV09A-8025U-B103_PTH_POT_27MM4_9MM7-MFG [mm]
  rrect6% 1.55x1.55 hole 1 paste-1000 mask+0: 1(-2.5,8)
  round 1.55 hole 1 paste-1000 mask+0: 2(0,8) 3(2.5,8)
  rrect100% 2.4x4.6 hole 4 slot 1.8 at 0 deg paste-1000 mask+0: 4(-5,11.3) 5(5,11.3)
  silkscreen extent -5.62,4.5 4.85,13.95, body extent -6.3,-14.05 6.3,14.05, height 0.25
FP-TSW-115-23-T-S-MFG [mm]
  rect 1.57x1.57 hole 1.02 paste-1000 mask+0: 1(-17.78,0)
  round 1.57 hole 1.02 paste-1000 mask+0: 2(-15.24,0) 3(-12.7,0) 4(-10.16,0) 5(-7.62,0) 6(-5.08,0) 7(-2.54,0) 8(0,0) 9(2.54,0) 10(5.08,0) 11(7.62,0) 12(10.16,0) 13(12.7,0) 14(15.24,0) 15(17.78,0)
  silkscreen extent -19.24,-1.95 19.24,1.34, body extent -19.34,-1.44 19.34,1.44, height 0.25
FP-TSW-117-23-T-S-MFG [mm]
  rect 1.57x1.57 hole 1.02 paste-1000 mask+0: 1(-20.32,0)
  round 1.57 hole 1.02 paste-1000 mask+0: 2(-17.78,0) 3(-15.24,0) 4(-12.7,0) 5(-10.16,0) 6(-7.62,0) 7(-5.08,0) 8(-2.54,0) 9(0,0) 10(2.54,0) 11(5.08,0) 12(7.62,0) 13(10.16,0) 14(12.7,0) 15(15.24,0) 16(17.78,0) 17(20.32,0)
  silkscreen extent -21.78,-1.95 21.78,1.34, body extent -21.88,-1.44 21.88,1.44, height 0.25
FP-TSW-127-23-T-S-MFG [mm]
  rect 1.57x1.57 hole 1.02 paste-1000 mask+0: 1(-33.02,0)
  round 1.57 hole 1.02 paste-1000 mask+0: 2(-30.48,0) 3(-27.94,0) 4(-25.4,0) 5(-22.86,0) 6(-20.32,0) 7(-17.78,0) 8(-15.24,0) 9(-12.7,0) 10(-10.16,0) 11(-7.62,0) 12(-5.08,0) 13(-2.54,0) 14(0,0) 15(2.54,0) 16(5.08,0) 17(7.62,0) 18(10.16,0) 19(12.7,0) 20(15.24,0) 21(17.78,0) 22(20.32,0) 23(22.86,0) 24(25.4,0) 25(27.94,0) 26(30.48,0) 27(33.02,0)
  silkscreen extent -35.14,-1.34 34.48,1.34, body extent -34.58,-1.44 34.58,1.44, height 0.25
FP-TSW-128-23-T-S-0 [mm]
  rect 1.57x1.57 hole 1.02 paste-1000 mask+0: 1(-34.29,0)
  round 1.57 hole 1.02 paste-1000 mask+0: 2(-31.75,0) 3(-29.21,0) 4(-26.67,0) 5(-24.13,0) 6(-21.59,0) 7(-19.05,0) 8(-16.51,0) 9(-13.97,0) 10(-11.43,0) 11(-8.89,0) 12(-6.35,0) 13(-3.81,0) 14(-1.27,0) 15(1.27,0) 16(3.81,0) 17(6.35,0) 18(8.89,0) 19(11.43,0) 20(13.97,0) 21(16.51,0) 22(19.05,0) 23(21.59,0) 24(24.13,0) 25(26.67,0) 26(29.21,0) 27(31.75,0) 28(34.29,0)
  silkscreen extent -35.75,-1.95 35.75,1.34, body extent -35.85,-1.44 35.85,1.44, height 0.25
FP-TSW-132-23-T-S-MFG [mm]
  rect 1.57x1.57 hole 1.02 paste-1000 mask+0: 1(-39.37,0)
  round 1.57 hole 1.02 paste-1000 mask+0: 2(-36.83,0) 3(-34.29,0) 4(-31.75,0) 5(-29.21,0) 6(-26.67,0) 7(-24.13,0) 8(-21.59,0) 9(-19.05,0) 10(-16.51,0) 11(-13.97,0) 12(-11.43,0) 13(-8.89,0) 14(-6.35,0) 15(-3.81,0) 16(-1.27,0) 17(1.27,0) 18(3.81,0) 19(6.35,0) 20(8.89,0) 21(11.43,0) 22(13.97,0) 23(16.51,0) 24(19.05,0) 25(21.59,0) 26(24.13,0) 27(26.67,0) 28(29.21,0) 29(31.75,0) 30(34.29,0) 31(36.83,0) 32(39.37,0)
  silkscreen extent -41.55,-1.34 40.83,1.34, body extent -40.93,-1.44 40.93,1.44, height 0.25
FP-TSW-133-23-T-S-MFG [mm]
  rect 1.57x1.57 hole 1.02 paste-1000 mask+0: 1(-40.64,0)
  round 1.57 hole 1.02 paste-1000 mask+0: 2(-38.1,0) 3(-35.56,0) 4(-33.02,0) 5(-30.48,0) 6(-27.94,0) 7(-25.4,0) 8(-22.86,0) 9(-20.32,0) 10(-17.78,0) 11(-15.24,0) 12(-12.7,0) 13(-10.16,0) 14(-7.62,0) 15(-5.08,0) 16(-2.54,0) 17(0,0) 18(2.54,0) 19(5.08,0) 20(7.62,0) 21(10.16,0) 22(12.7,0) 23(15.24,0) 24(17.78,0) 25(20.32,0) 26(22.86,0) 27(25.4,0) 28(27.94,0) 29(30.48,0) 30(33.02,0) 31(35.56,0) 32(38.1,0) 33(40.64,0)
  silkscreen extent -42.1,-1.95 42.1,1.34, body extent -42.2,-1.44 42.2,1.44, height 0.25
LP-M67K_Green [mm] "Osram"
  rect 0.8x1 smd: 1(-1,0) 2(1,0)
  silkscreen extent -0.3,-0.75 1.78,0.75, body extent -1.15,-0.75 1.15,0.75, height 1.4
MHNP_M3_PANHEAD_PHILLIPS#1 [mil]
  round 121 hole 126 unplated mask+5.5: ""(0,0)
  Keep-Out Layer circle w1: c0,0 r126
MHNP_M3_PANHEAD_PHILLIPS#2 [mil]
  round 245 hole 250 unplated mask+5.5: ""(0,0)
  Keep-Out Layer circle w1: c0,0 r126
Molex_0022284033 [mm] "Header, 2.54mm, 3x1, TH"
  rect 1.55x1.55 hole 1.02: 1(-2.54,0)
  round 1.55 hole 1.02: 2(0,0) 3(2.54,0)
  silkscreen extent -3.81,-1.24 3.81,1.5, body extent -3.81,-1.24 3.81,1.24, height 8.4
MSPL_GPMC_MOD [mil]
  rect 61x24 smd mask+3: 1(-393.7,325) 2(-393.7,275) 3(-393.7,225) 4(-393.7,175) 5(-393.7,125) 6(-393.7,75) 7(-393.7,25) 8(-393.7,-25) 9(-393.7,-75) 10(-393.7,-125) 11(-393.7,-175) 12(-393.7,-225) 13(-393.7,-275) 14(-393.7,-325) 29(393.7,-325) 30(393.7,-275) 31(393.7,-225) 32(393.7,-175) 33(393.7,-125) 34(393.7,-75) 35(393.7,-25) 36(393.7,25) 37(393.7,75) 38(393.7,125) 39(393.7,175) 40(393.7,225) 41(393.7,275) 42(393.7,325)
  rect 24x61 smd mask+3: 15(-325,-393.7) 16(-275,-393.7) 17(-225,-393.7) 18(-175,-393.7) 19(-125,-393.7) 20(-75,-393.7) 21(-25,-393.7) 22(25,-393.7) 23(75,-393.7) 24(125,-393.7) 25(175,-393.7) 26(225,-393.7) 27(275,-393.7) 28(325,-393.7) 43(325,393.7) 44(275,393.7) 45(225,393.7) 46(175,393.7) 47(125,393.7) 48(75,393.7) 49(25,393.7) 50(-25,393.7) 51(-75,393.7) 52(-125,393.7) 53(-175,393.7) 54(-225,393.7) 55(-275,393.7) 56(-325,393.7)
  silkscreen extent -450,-405 405,405, body extent -395,-395 395,395, height 59
ONSC-SOT-23-3-318-08_V [mm] "SOT23, 3-Leads, Body 2.92x1.3mm, Pitch 0.95mm"
  rect 0.9x0.8 smd: 1(-1,0.95) 2(-1,-0.95) 3(1,0)
  silkscreen extent -1.13,-1.46 0.65,2.02, body extent -0.65,-1.46 0.65,1.46, height 1.11
PW0016A_L [mm] "TSOP, 16-Leads, Body 5x4.4mm, Pitch 0.65mm, IPC High Density"
  oval 1.2x0.4 smd: 1(-2.85,2.275) 2(-2.85,1.625) 3(-2.85,0.975) 4(-2.85,0.325) 5(-2.85,-0.325) 6(-2.85,-0.975) 7(-2.85,-1.625) 8(-2.85,-2.275) 9(2.85,-2.275) 10(2.85,-1.625) 11(2.85,-0.975) 12(2.85,-0.325) 13(2.85,0.325) 14(2.85,0.975) 15(2.85,1.625) 16(2.85,2.275)
  silkscreen extent -2,-2.55 1.85,2.55, body extent -3.21,-2.5 3.21,2.5, height 1
RUA0042A-MFG [mm]
  rrect40% 0.6x0.25 smd paste+0 mask+0: 1(-1.65,4) 2(-1.65,3.5) 3(-1.65,3) 4(-1.65,2.5) 5(-1.65,2) 6(-1.65,1.5) 7(-1.65,1) 8(-1.65,0.5) 9(-1.65,0) 10(-1.65,-0.5) 11(-1.65,-1) 12(-1.65,-1.5) 13(-1.65,-2) 14(-1.65,-2.5) 15(-1.65,-3) 16(-1.65,-3.5) 17(-1.65,-4) 22(1.65,-4) 23(1.65,-3.5) 24(1.65,-3) 25(1.65,-2.5) 26(1.65,-2) 27(1.65,-1.5) 28(1.65,-1) 29(1.65,-0.5) 30(1.65,0) 31(1.65,0.5) 32(1.65,1) 33(1.65,1.5) 34(1.65,2) 35(1.65,2.5) 36(1.65,3) 37(1.65,3.5) 38(1.65,4)
  rrect40% 0.25x0.6 smd paste+0 mask+0: 18(-0.75,-4.4) 19(-0.25,-4.4) 20(0.25,-4.4) 21(0.75,-4.4) 39(0.75,4.4) 40(0.25,4.4) 41(-0.25,4.4) 42(-0.75,4.4)
  rrect5% 2.05x7.55 smd paste-1000 mask+0: 43(0,0)
  silkscreen extent -2.65,-4.55 1.8,4.55, body extent -1.75,-4.5 1.75,4.5, height 0.8
RWB0012A [mm] "QFN, 12-Leads, Body 1.6x1.6mm, Pitch 0.4mm"
  rrect57% 0.7x0.2 smd paste-0.1: 1(-0.65,0.2) 2(-0.65,-0.2) 7(0.65,-0.2) 8(0.65,0.2)
  rrect57% 0.2x0.5 smd: 3(-0.6,-0.75) 4(-0.2,-0.75) 5(0.2,-0.75) 6(0.6,-0.75) 9(0.6,0.75) 10(0.2,0.75) 11(-0.2,0.75) 12(-0.6,0.75)
  silkscreen extent -0.92,-0.91 0.92,0.91, body extent -0.8,-0.8 0.8,0.8, height 0.4
Samtec_QSH-030-01-X-D-A [mm] "Receptacle, 0.5 mm, 30x2, TH"
  rect 2.27x0.279 smd: 1(-2.865,7.25) 2(2.865,7.25) 3(-2.865,6.75) 4(2.865,6.75) 5(-2.865,6.25) 6(2.865,6.25) 7(-2.865,5.75) 8(2.865,5.75) 9(-2.865,5.25) 10(2.865,5.25) 11(-2.865,4.75) 12(2.865,4.75) 13(-2.865,4.25) 14(2.865,4.25) 15(-2.865,3.75) 16(2.865,3.75) 17(-2.865,3.25) 18(2.865,3.25) 19(-2.865,2.75) 20(2.865,2.75) 21(-2.865,2.25) 22(2.865,2.25) 23(-2.865,1.75) 24(2.865,1.75) 25(-2.865,1.25) 26(2.865,1.25) 27(-2.865,0.75) 28(2.865,0.75) 29(-2.865,0.25) 30(2.865,0.25) 31(-2.865,-0.25) 32(2.865,-0.25) 33(-2.865,-0.75) 34(2.865,-0.75) 35(-2.865,-1.25) 36(2.865,-1.25) 37(-2.865,-1.75) 38(2.865,-1.75) 39(-2.865,-2.25) 40(2.865,-2.25) 41(-2.865,-2.75) 42(2.865,-2.75) 43(-2.865,-3.25) 44(2.865,-3.25) 45(-2.865,-3.75) 46(2.865,-3.75) 47(-2.865,-4.25) 48(2.865,-4.25) 49(-2.865,-4.75) 50(2.865,-4.75) 51(-2.865,-5.25) 52(2.865,-5.25) 53(-2.865,-5.75) 54(2.865,-5.75) 55(-2.865,-6.25) 56(2.865,-6.25) 57(-2.865,-6.75) 58(2.865,-6.75) 59(-2.865,-7.25) 60(2.865,-7.25)
  round 0 hole 1.02 unplated: MH1(2.67,10.065) MH2(2.67,-10.065)
  rect 0.43x2.54 smd: MP1(0,8.065) MP4(0,-8.065)
  rect 0.43x4.7 smd: MP2(0,3.175) MP3(0,-3.175)
  silkscreen extent -3.9,-10.66 3.62,10.66, body extent -3.75,-10.64 3.75,10.67, height 3.25
Samtec_TSM-107-01-x-DV [mm] "Header, 2.54mm, 7x2, SMT"
  rect 3.68x1.27 smd: 1(-2.475,7.62) 2(2.475,7.62) 3(-2.475,5.08) 4(2.475,5.08) 5(-2.475,2.54) 6(2.475,2.54) 7(-2.475,0) 8(2.475,0) 9(-2.475,-2.54) 10(2.475,-2.54) 11(-2.475,-5.08) 12(2.475,-5.08) 13(-2.475,-7.62) 14(2.475,-7.62)
  silkscreen extent -1.65,-8.89 1.65,9.03, body extent -3.85,-8.89 3.85,8.89, height 9.65
Samtec_TSW-101-08-x-S [mm] "Header, 2.54mm, 1x1, TH"
  round 1.53 hole 1.02: 1(0,0)
  body extent -1.27,-1.27 1.27,1.27, height 8.38
Samtec_TSW-102-08-x-S [mm] "Header, 2.54mm, 2x1, TH"
  rrect50% 1.53x1.53 hole 1.02: 1(-1.27,0)
  round 1.53 hole 1.02: 2(1.27,0)
  silkscreen extent -2.67,-1.27 2.54,1.7, body extent -2.67,-1.27 2.54,1.27, height 8.38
